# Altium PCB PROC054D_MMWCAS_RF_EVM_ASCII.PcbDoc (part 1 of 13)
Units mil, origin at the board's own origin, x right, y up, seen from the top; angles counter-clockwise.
Board outline 6299.21 x 5370.07 mil, 8 copper layers (L1 TOP, L2 GND, L3 SIGNAL 1, L4 GND, L5 SIGNAL 2, L6 SIGNAL 3, L7 GND, L8 BOTTOM), stack 53.5 mil thick; 775 components, 552 nets, 2648 pads, 7845 vias.
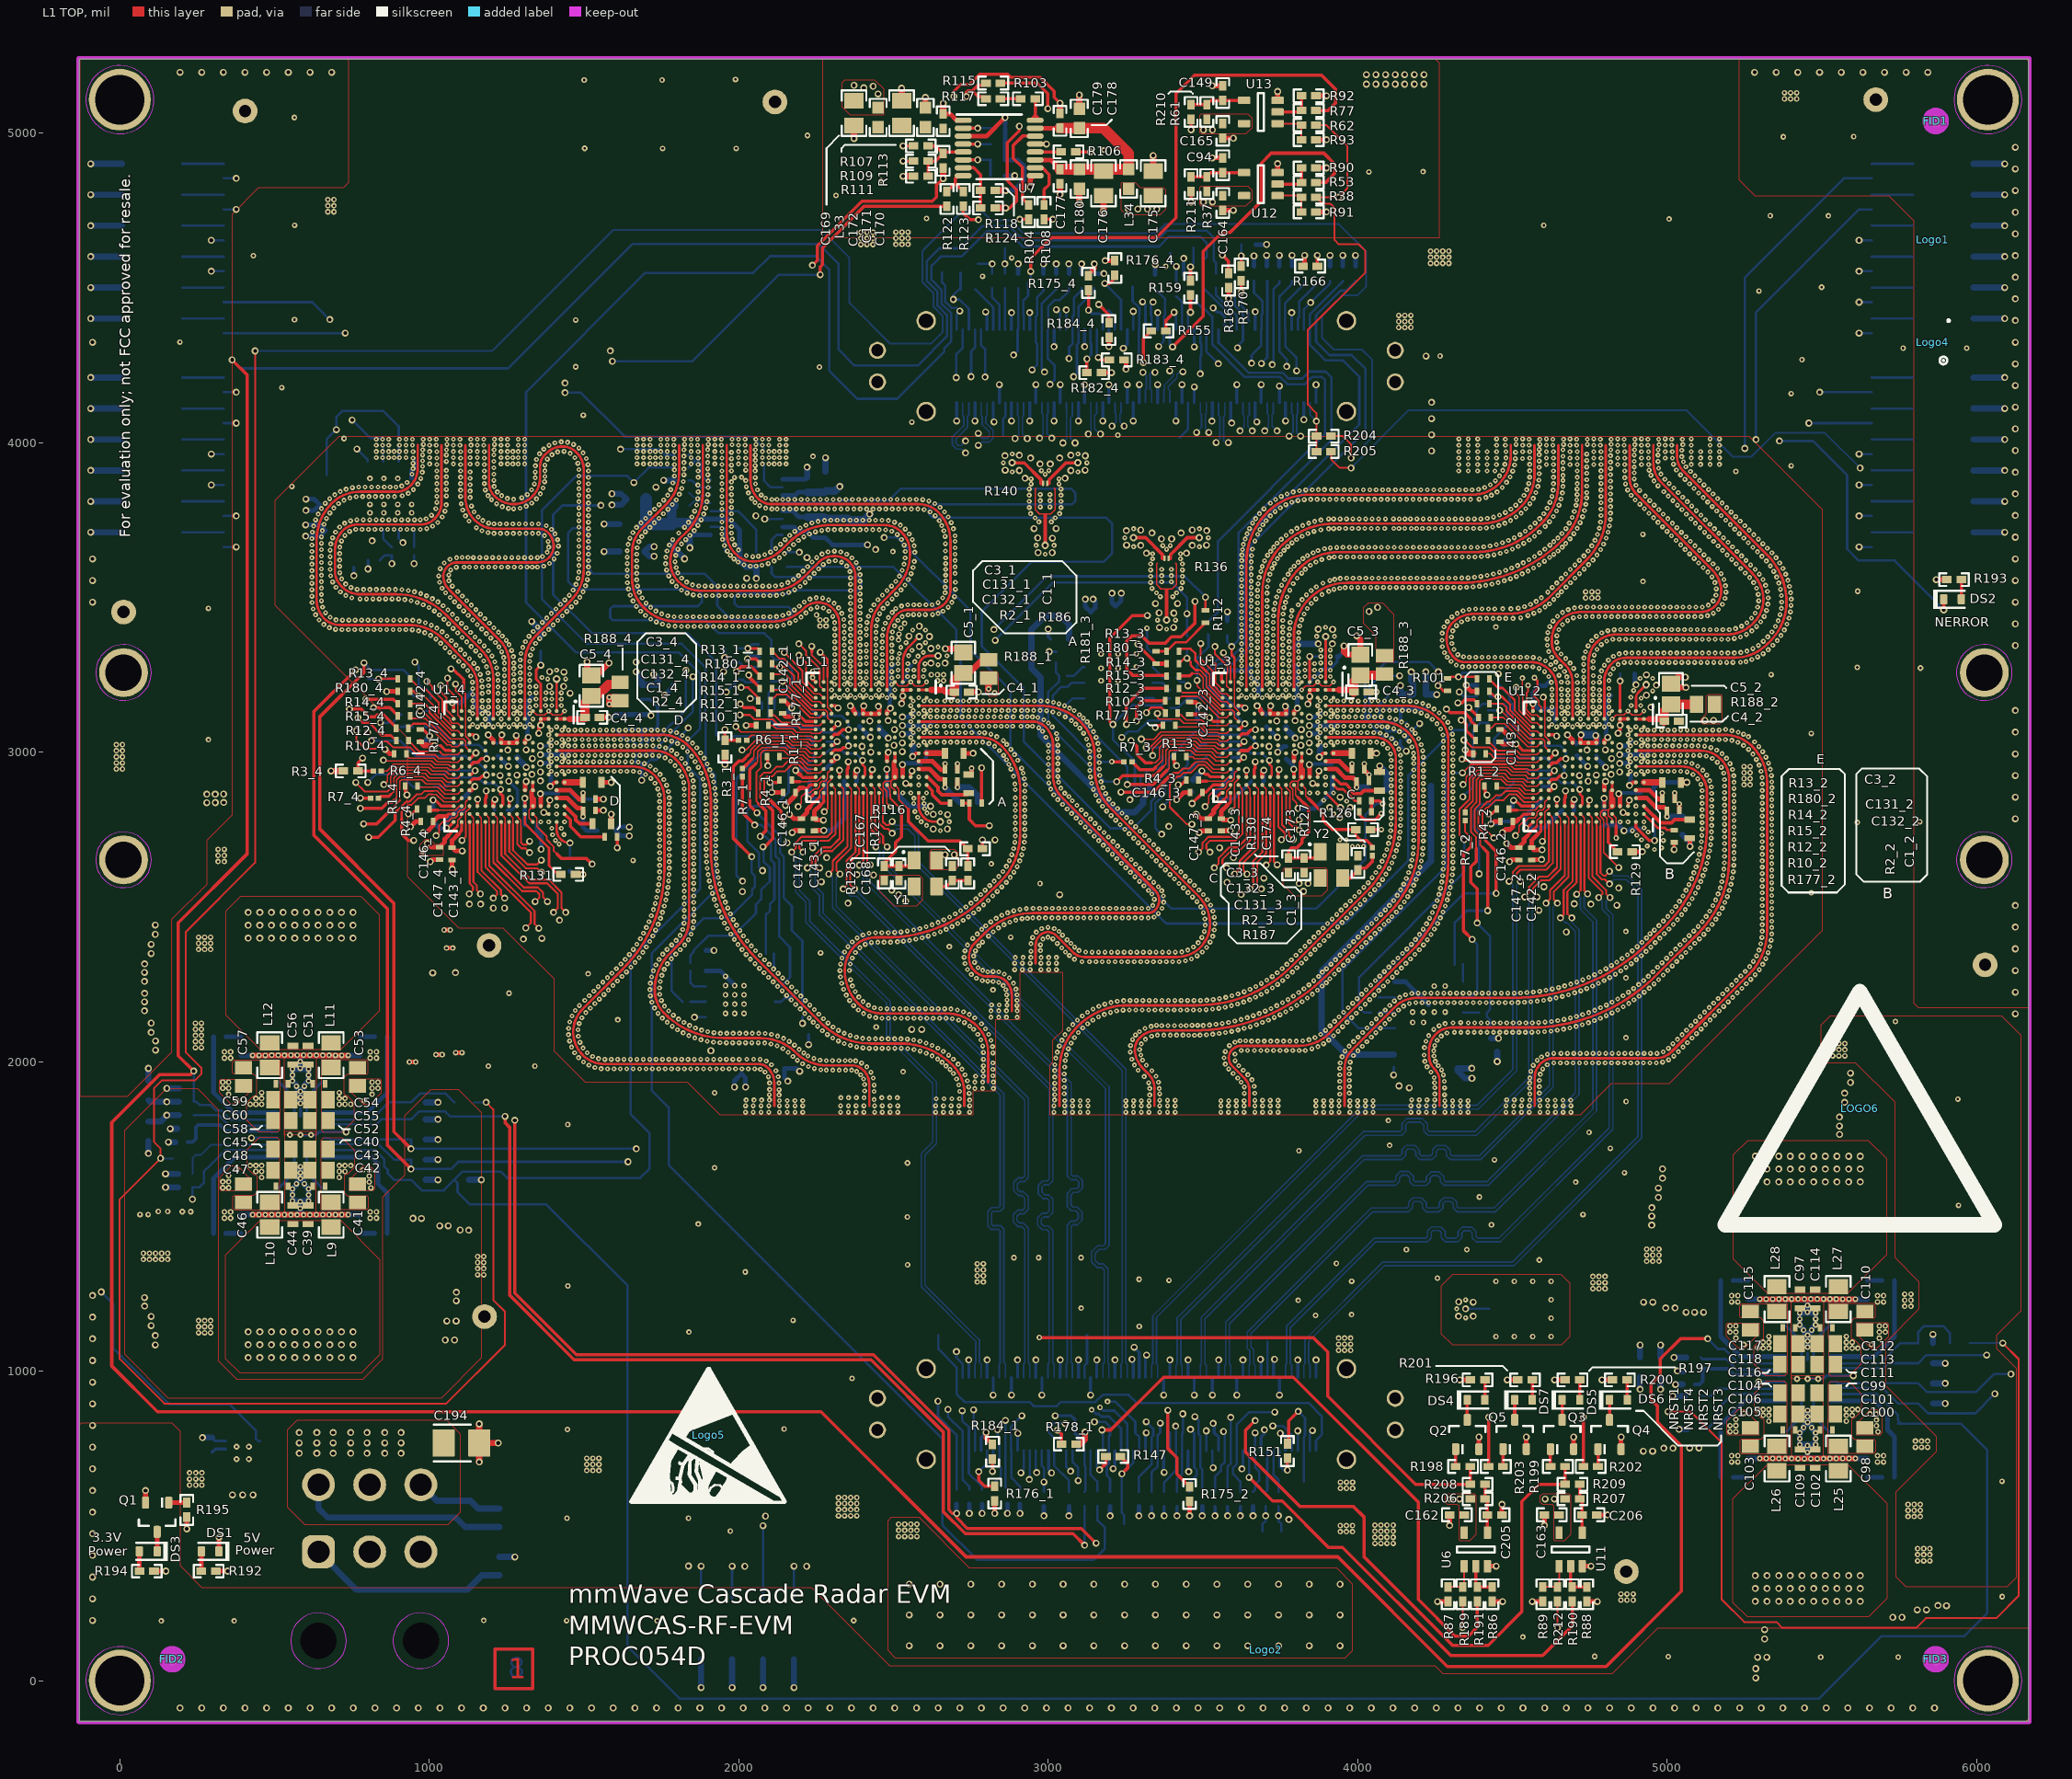
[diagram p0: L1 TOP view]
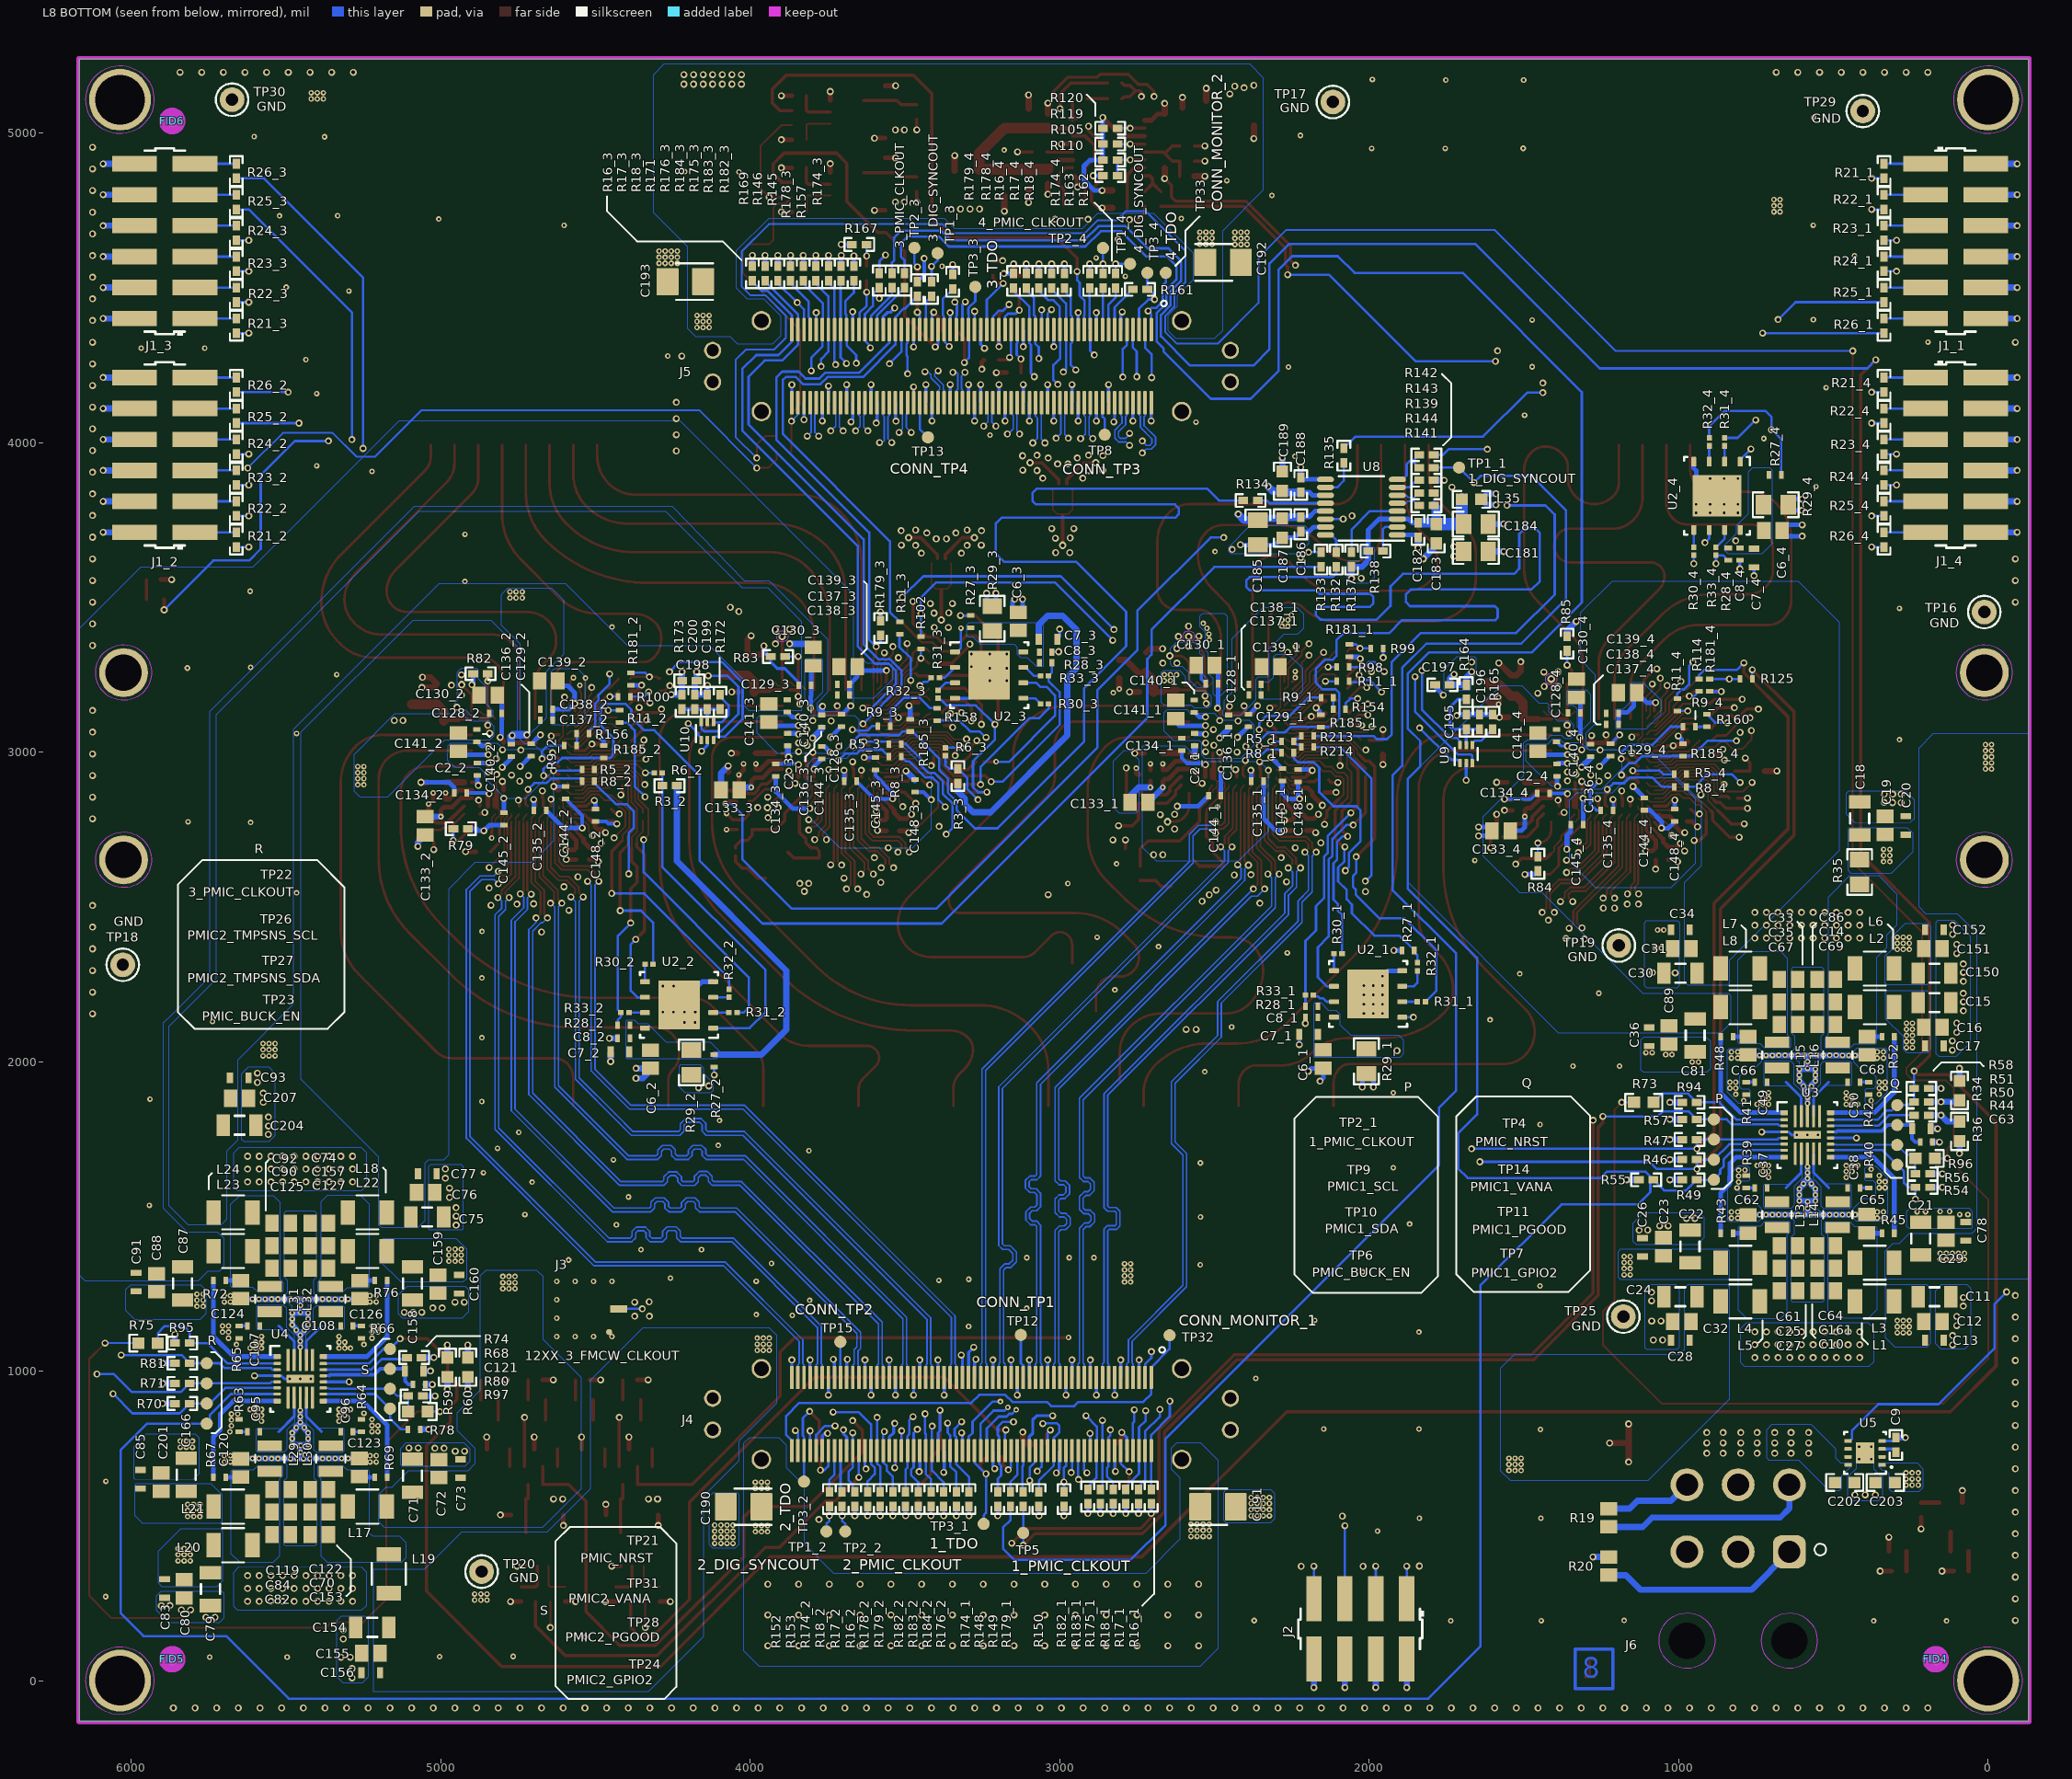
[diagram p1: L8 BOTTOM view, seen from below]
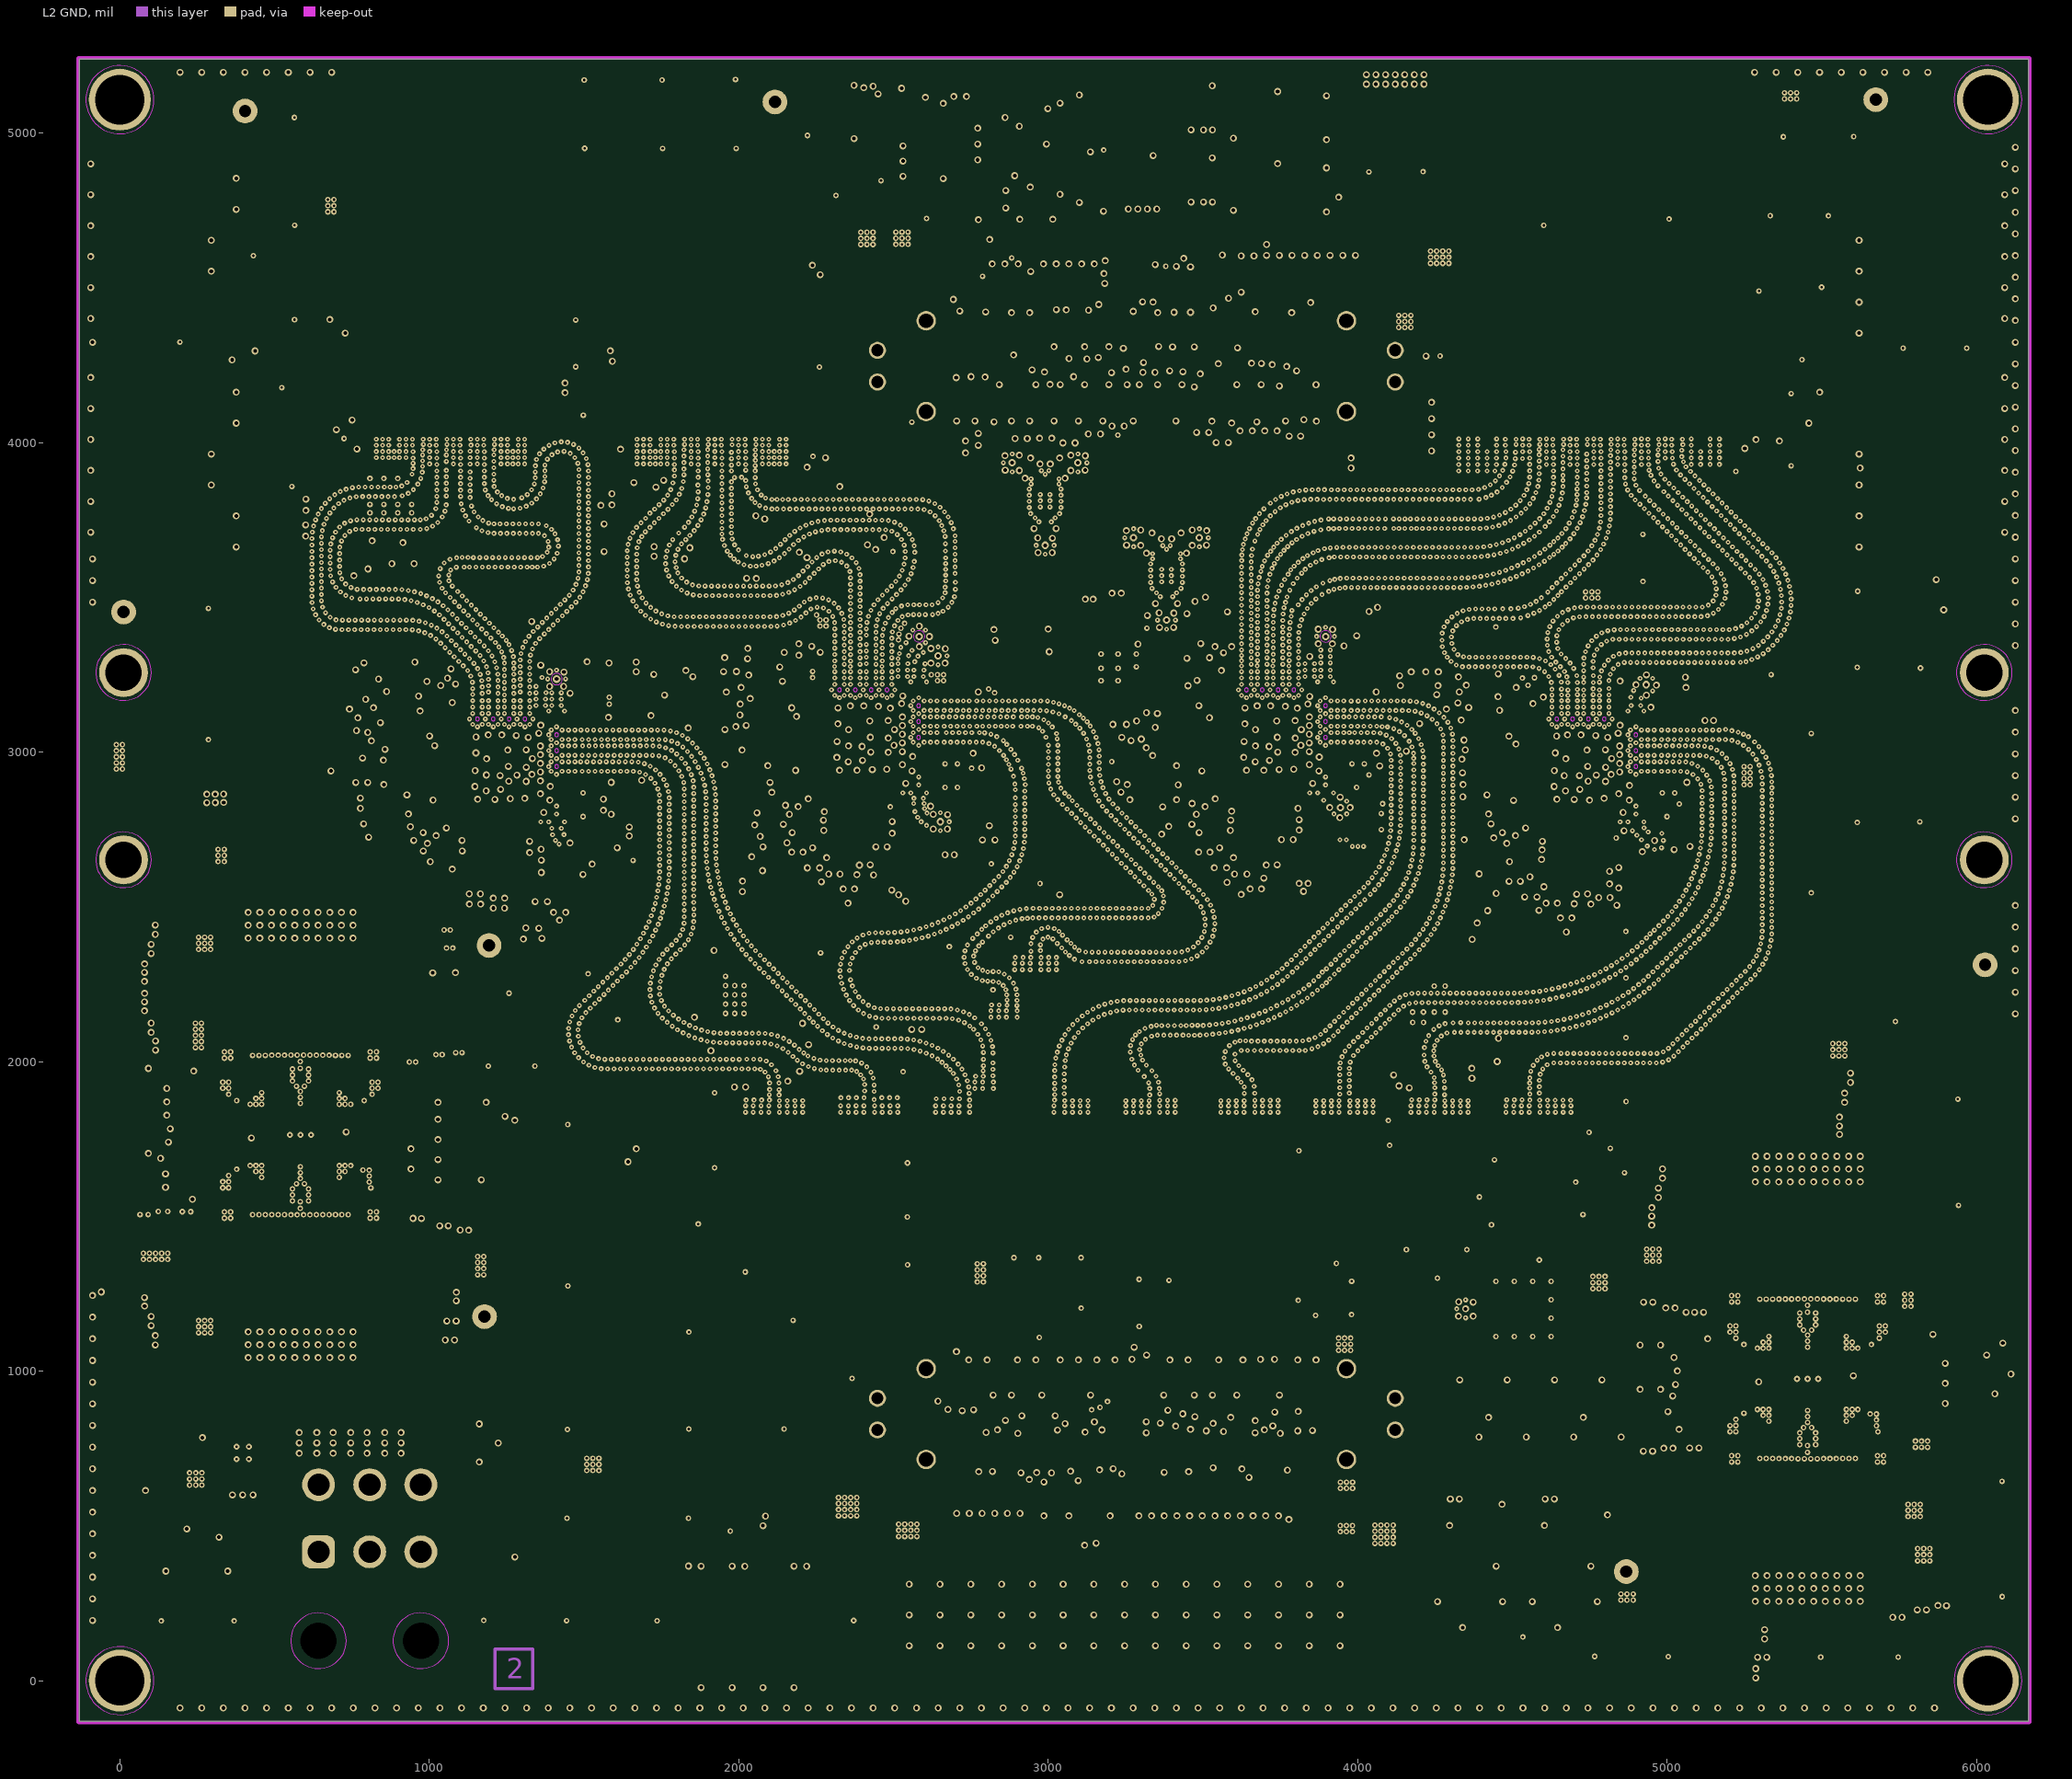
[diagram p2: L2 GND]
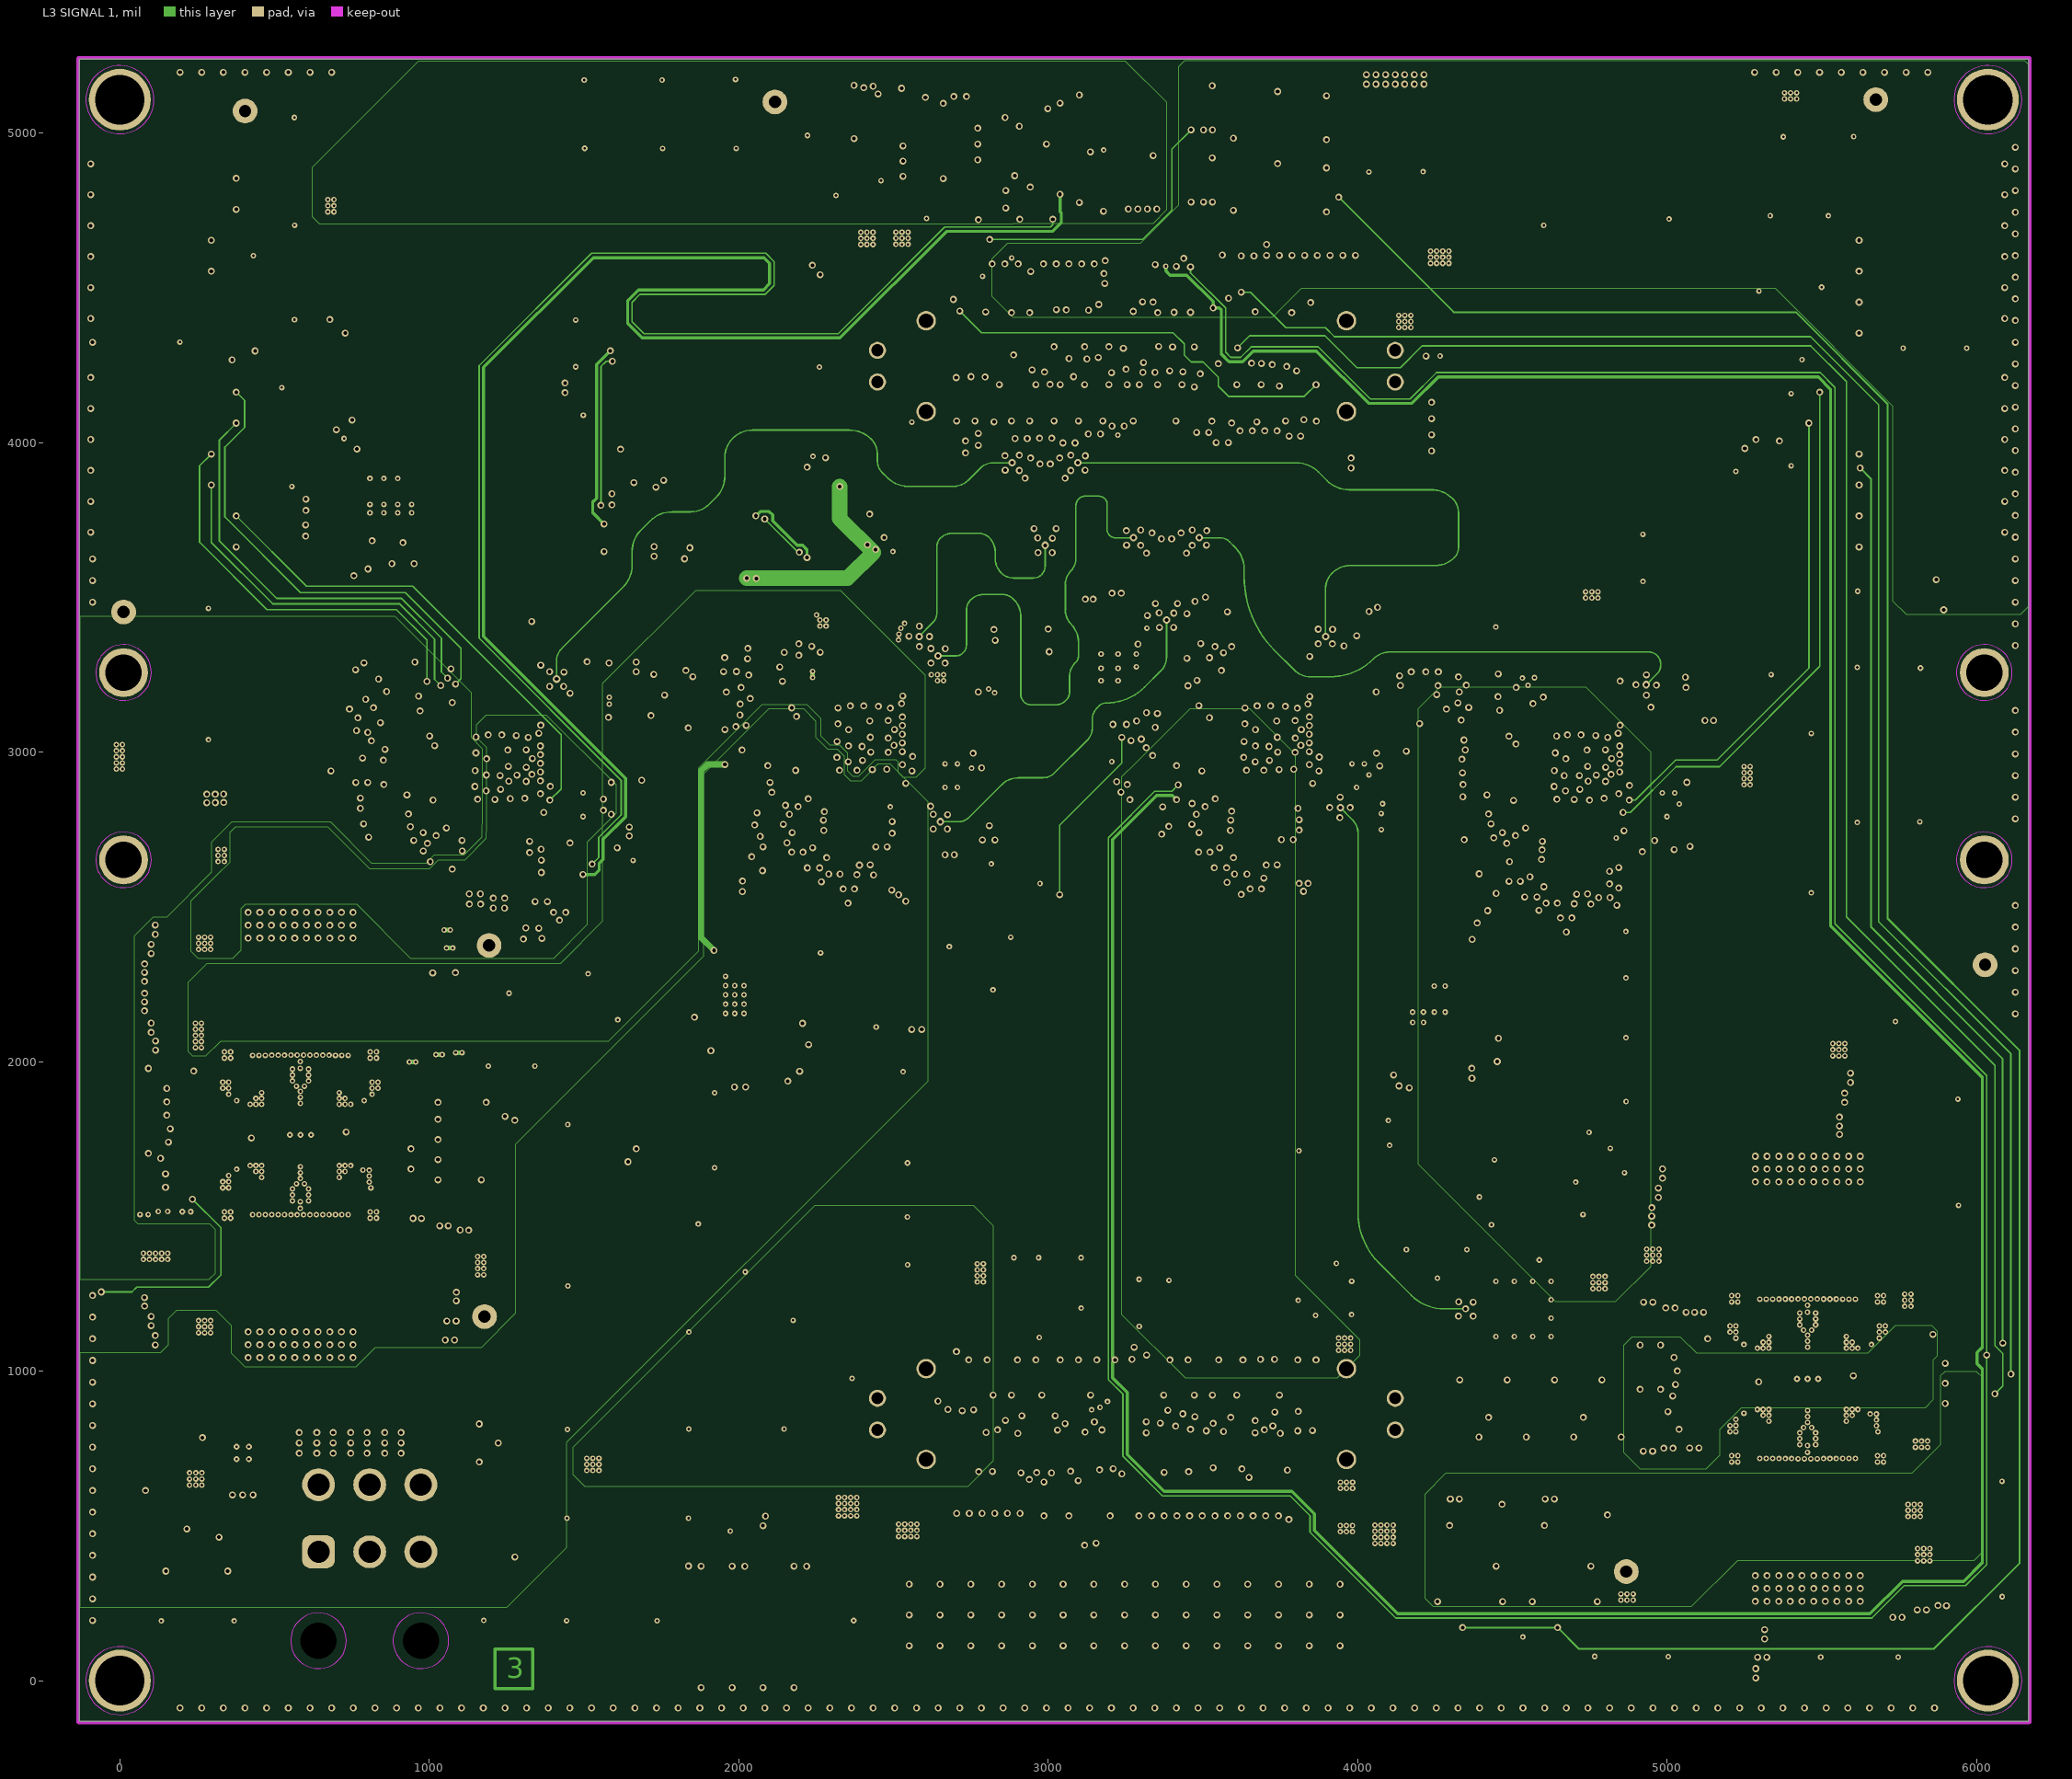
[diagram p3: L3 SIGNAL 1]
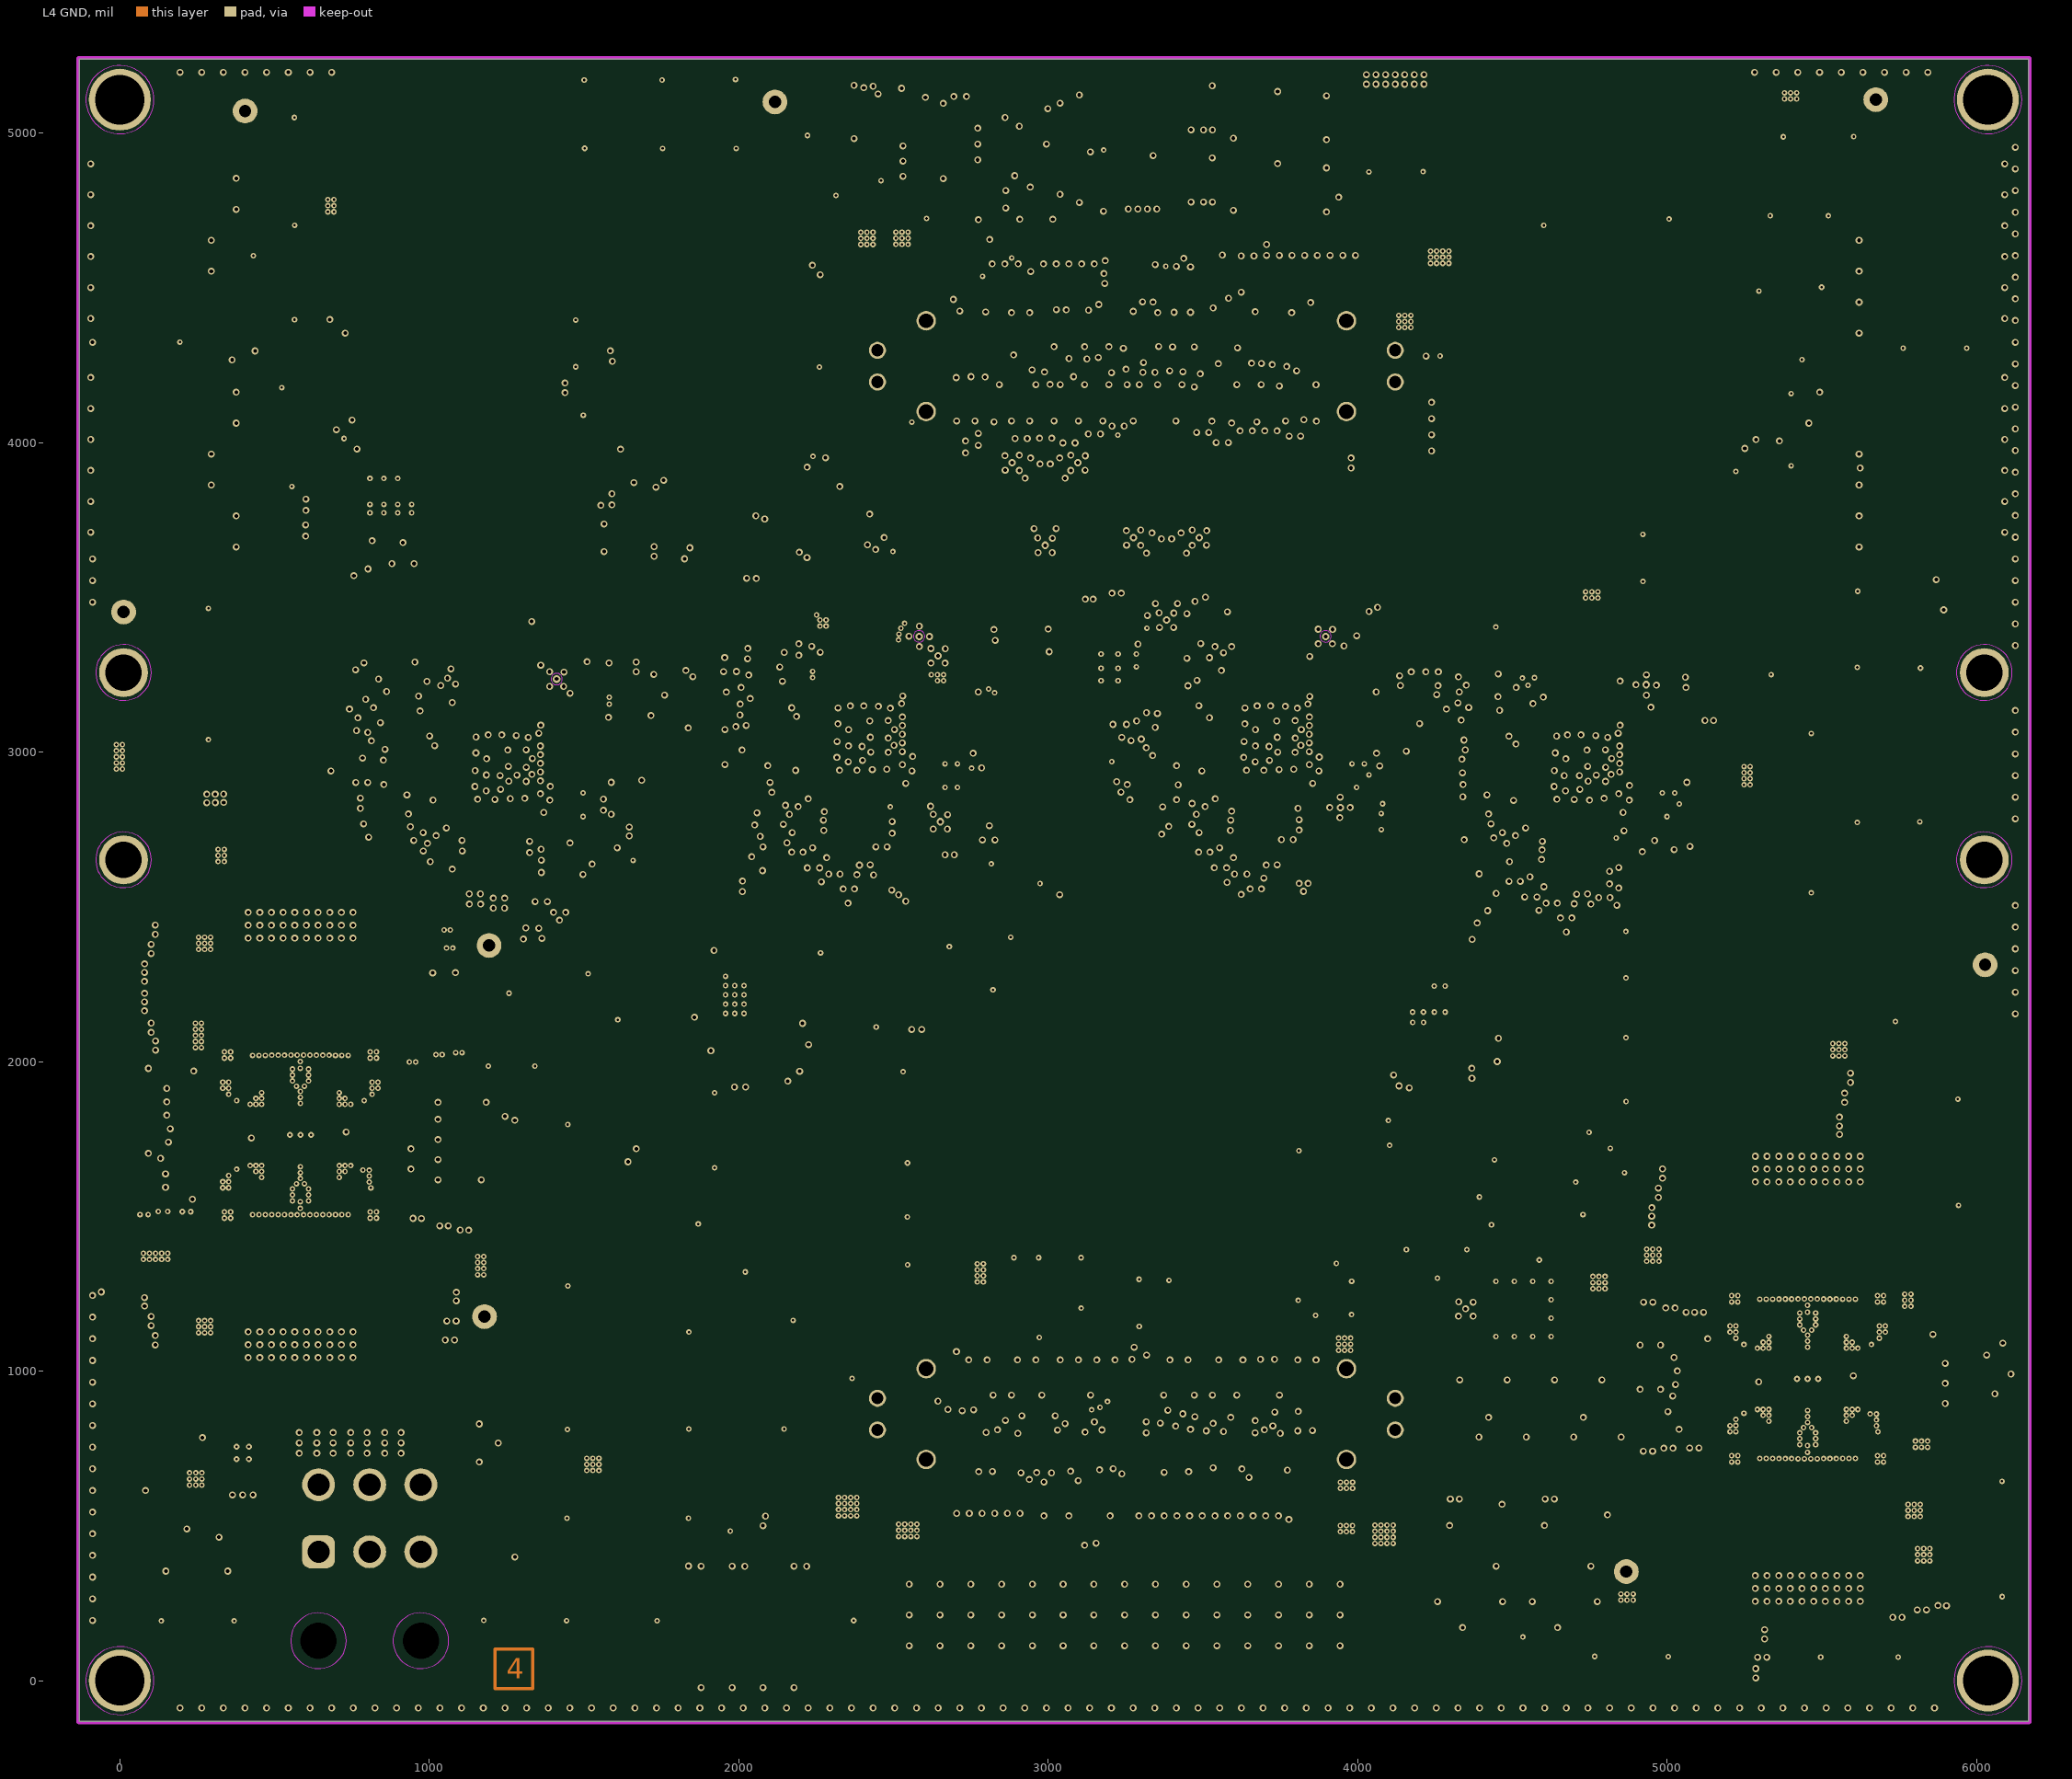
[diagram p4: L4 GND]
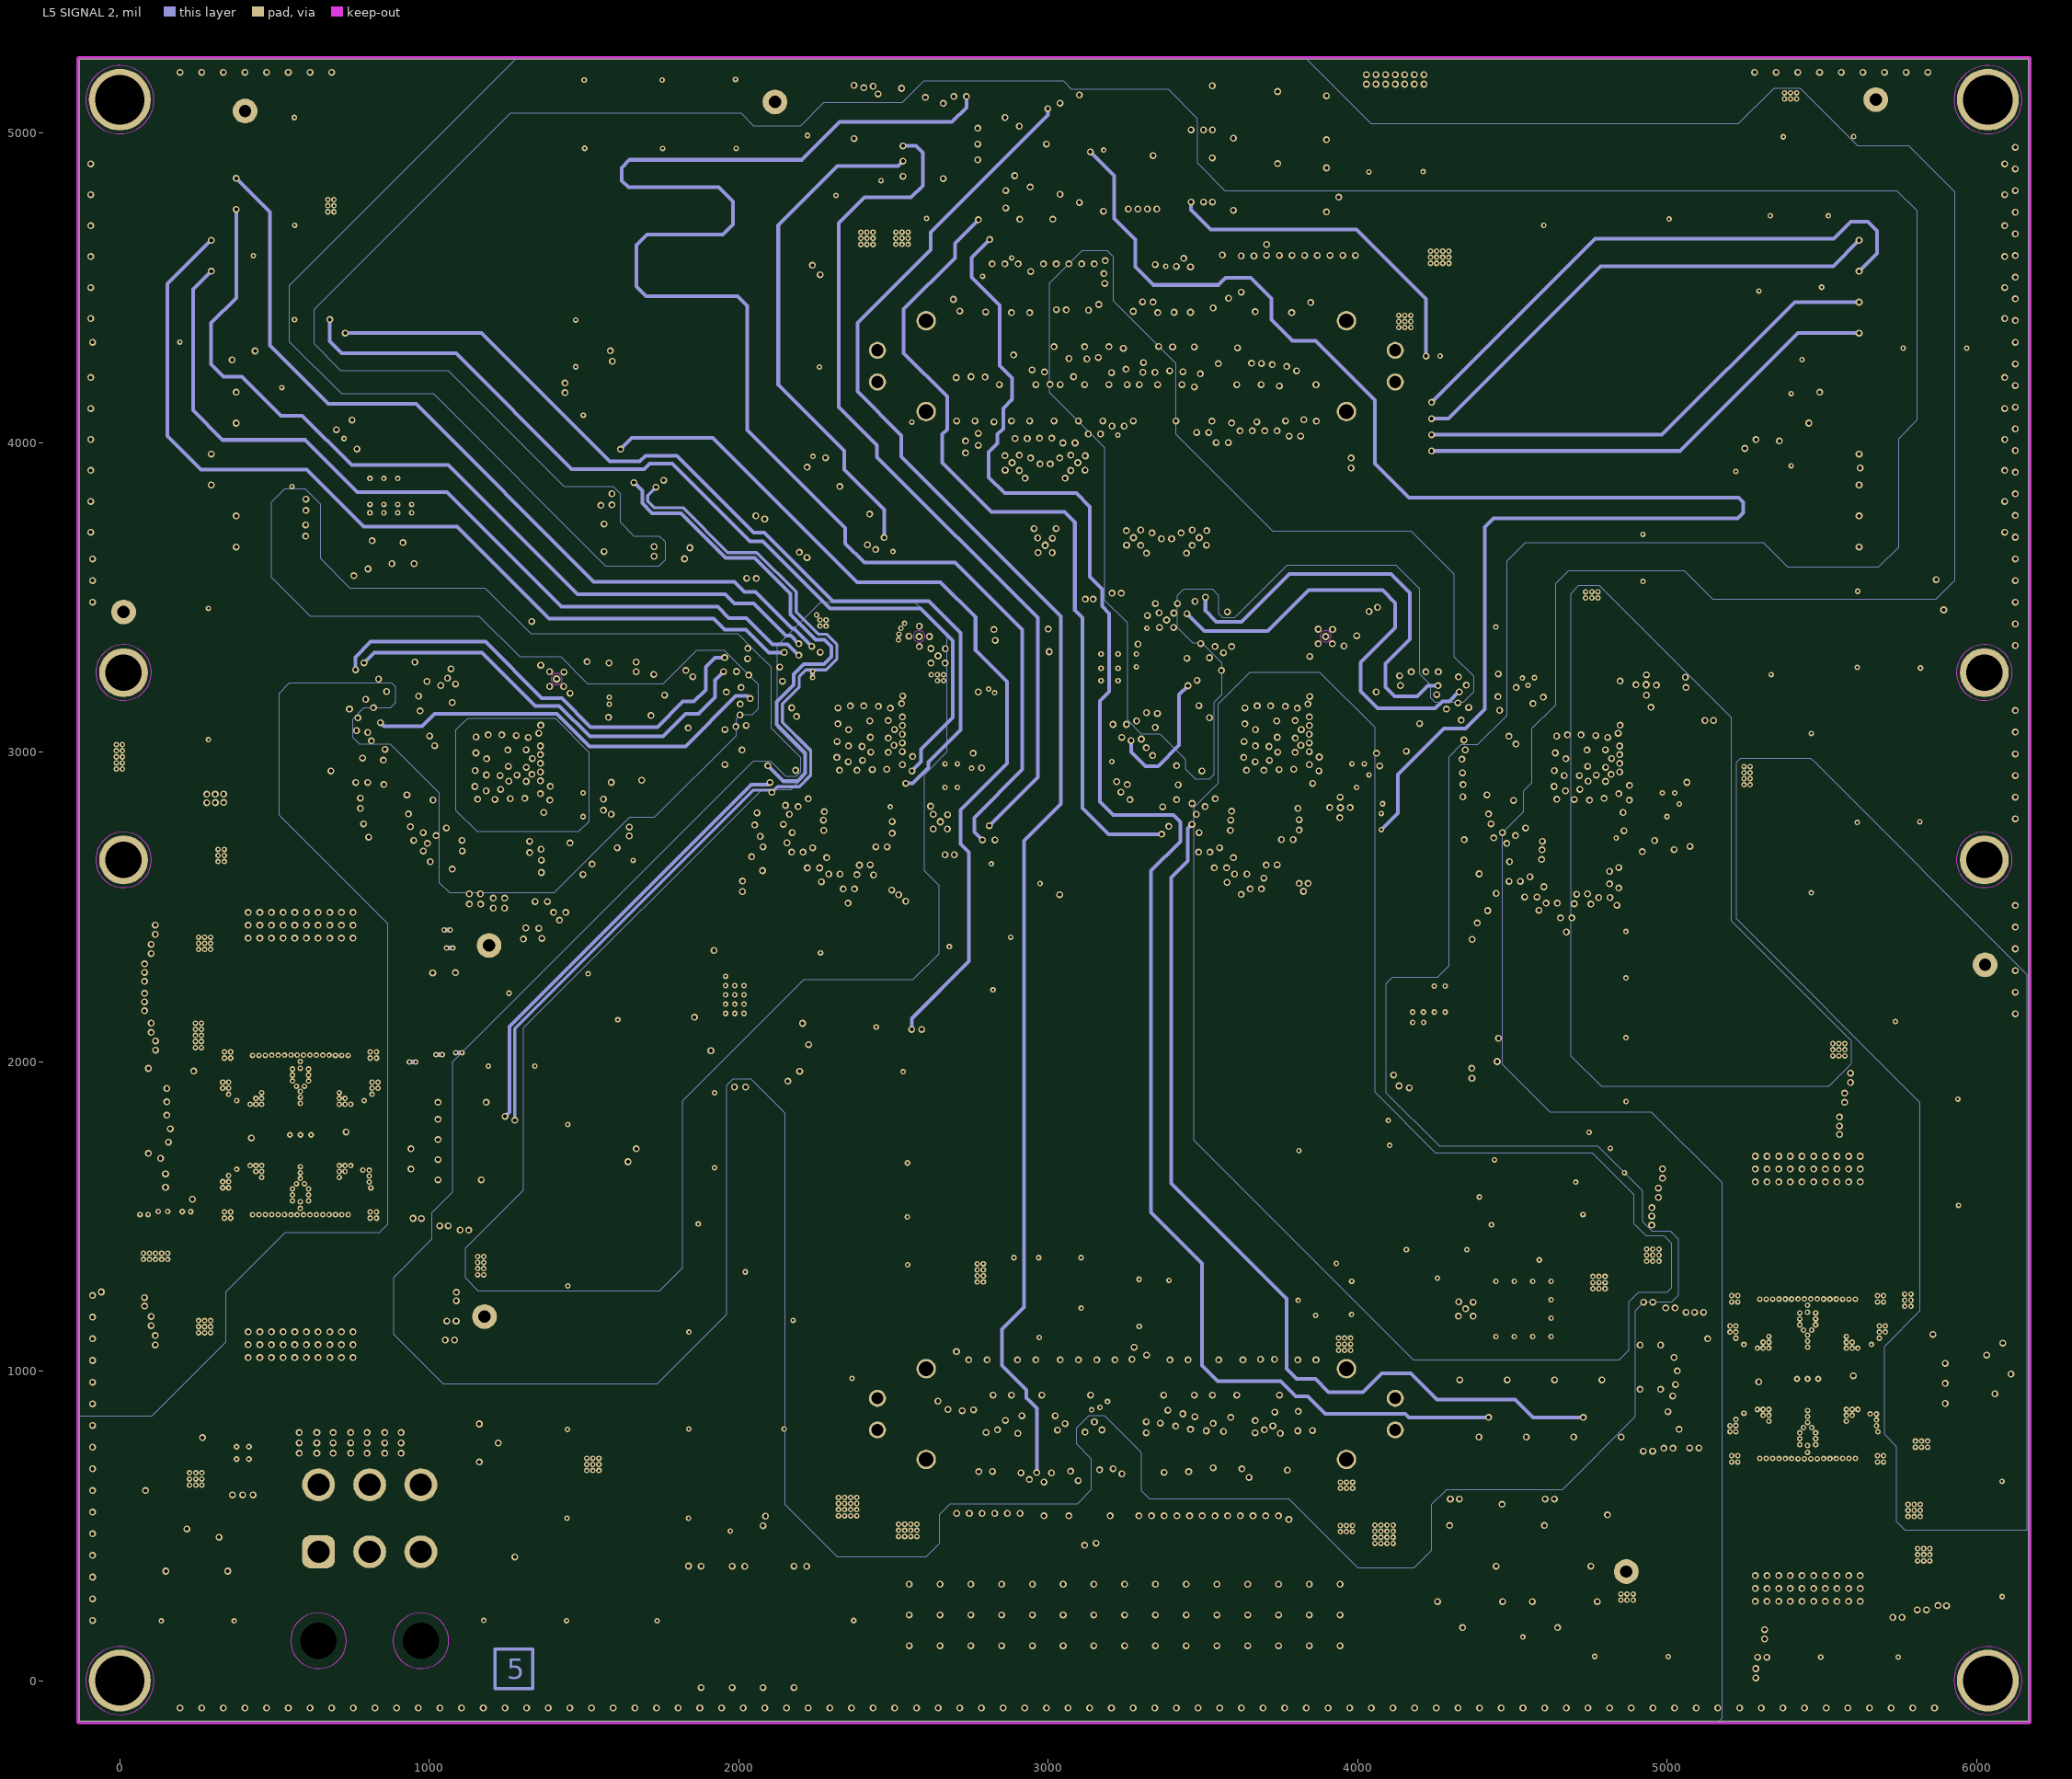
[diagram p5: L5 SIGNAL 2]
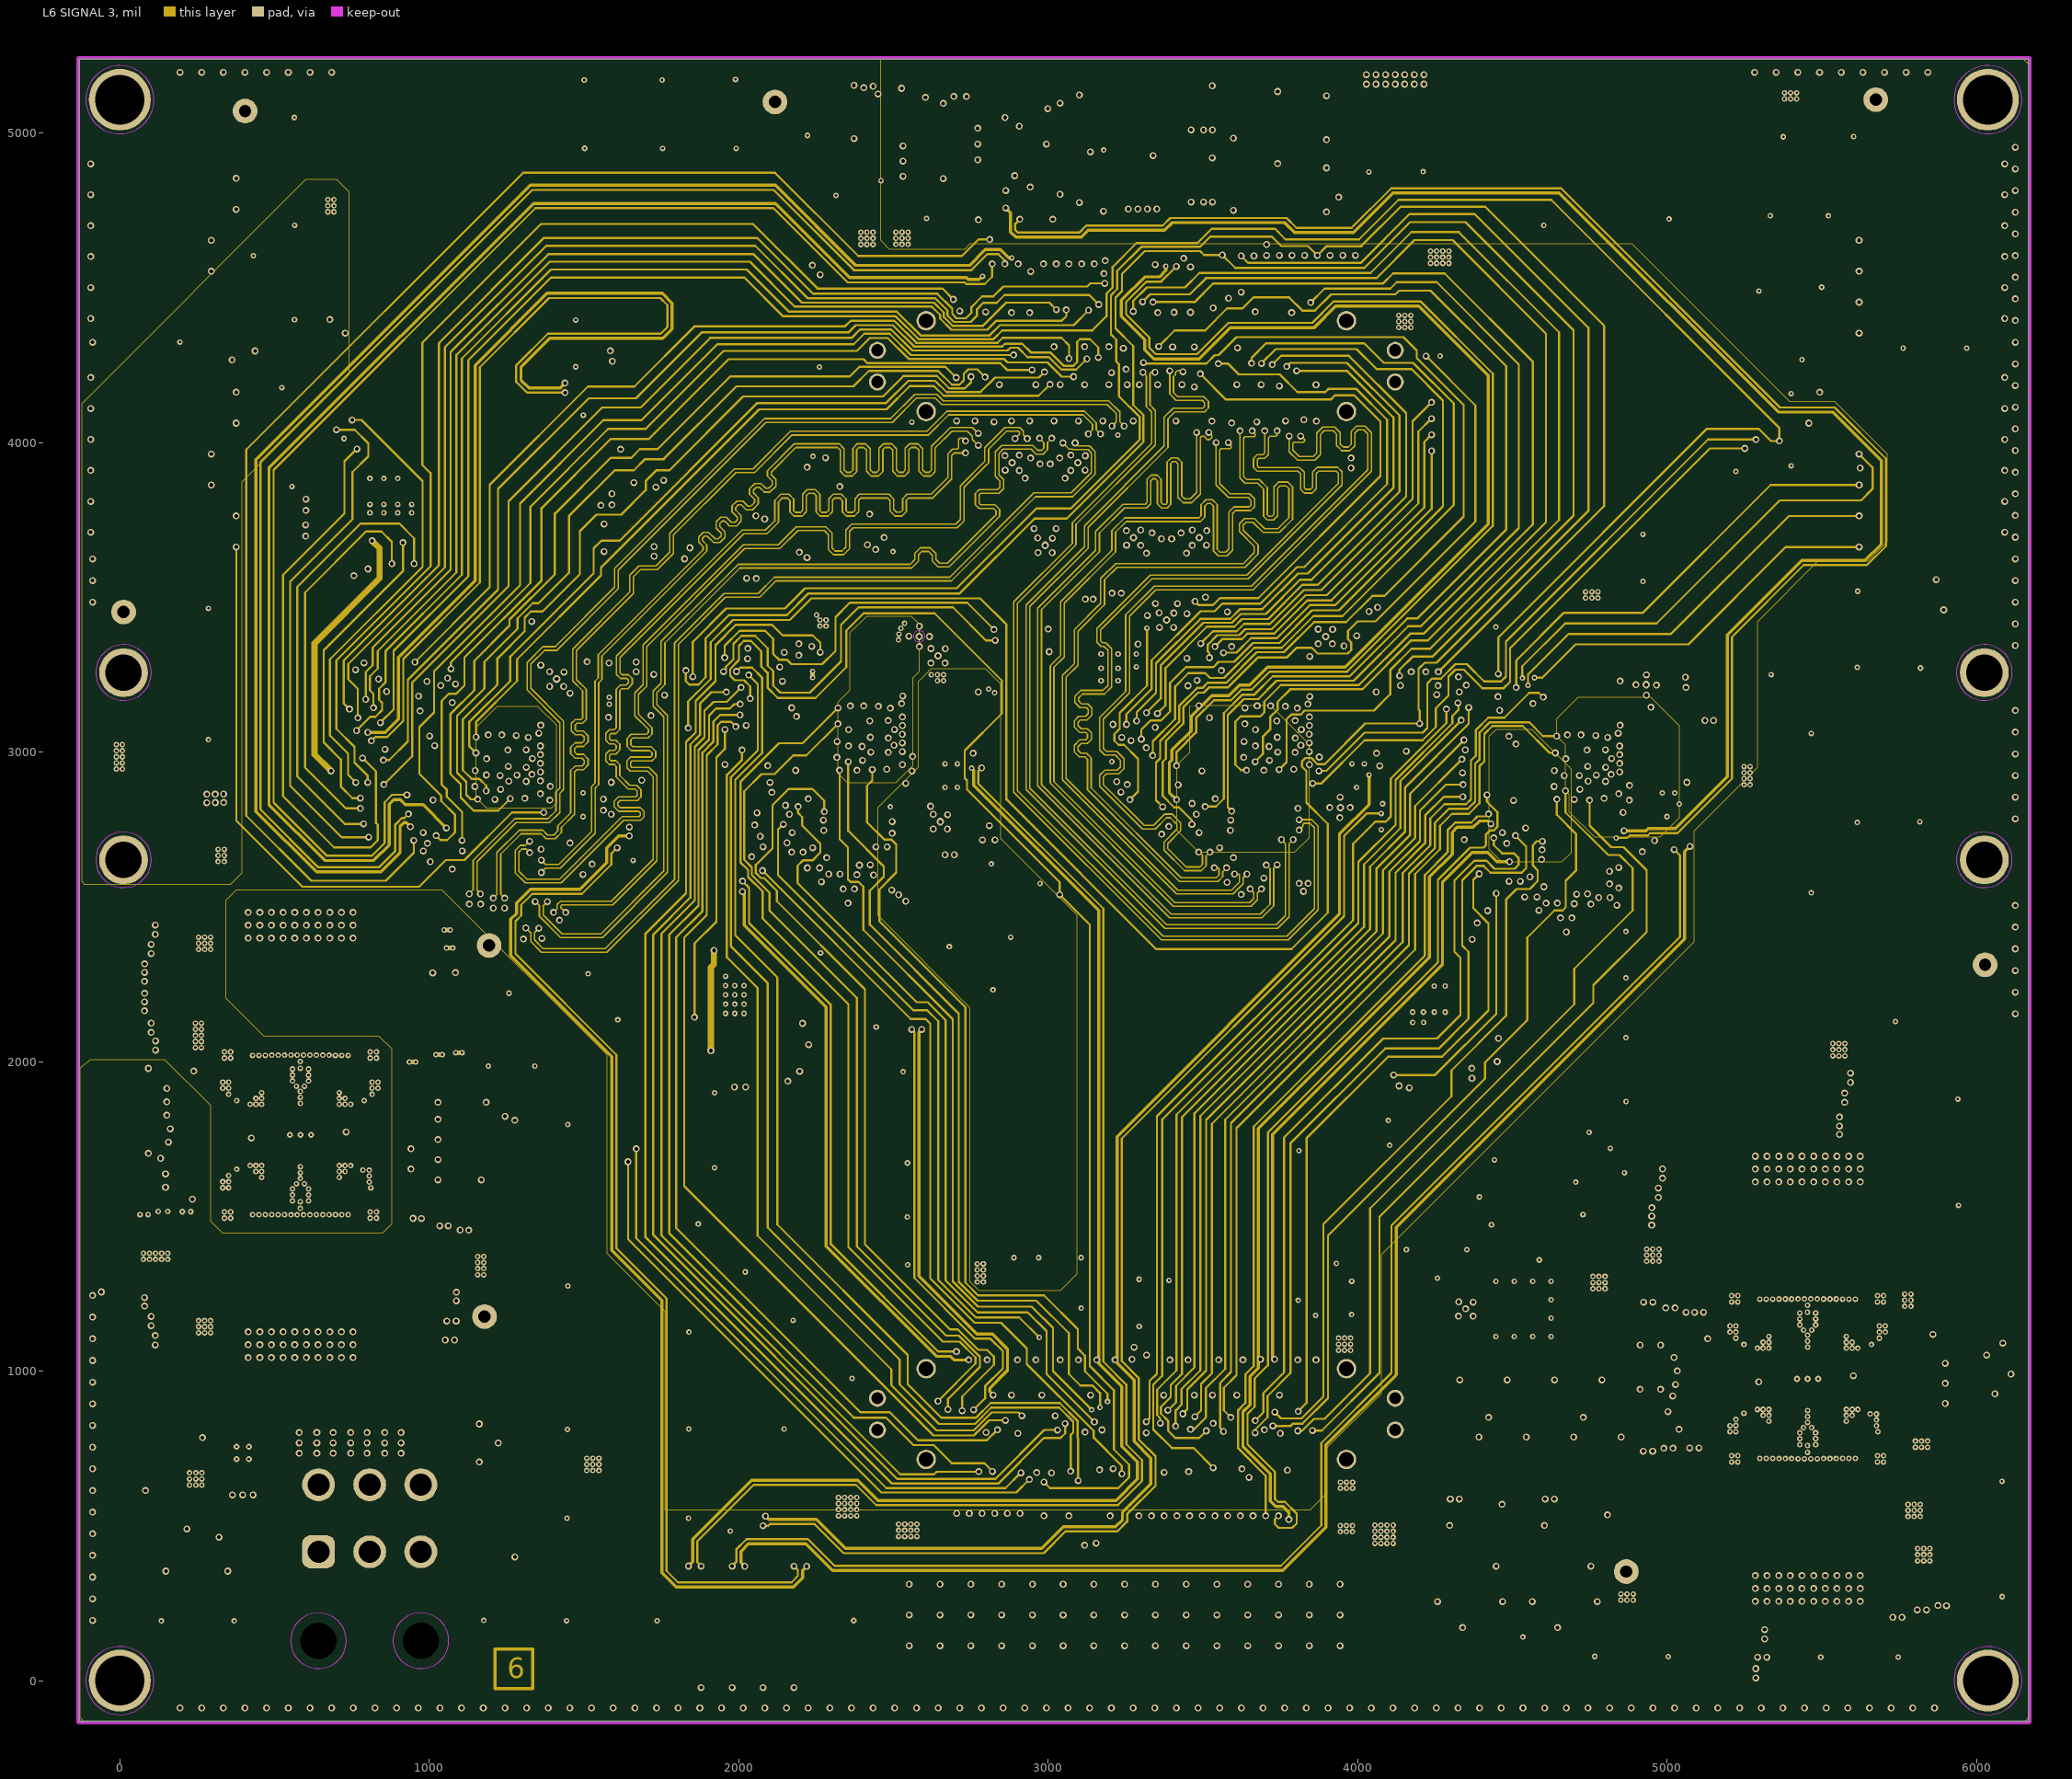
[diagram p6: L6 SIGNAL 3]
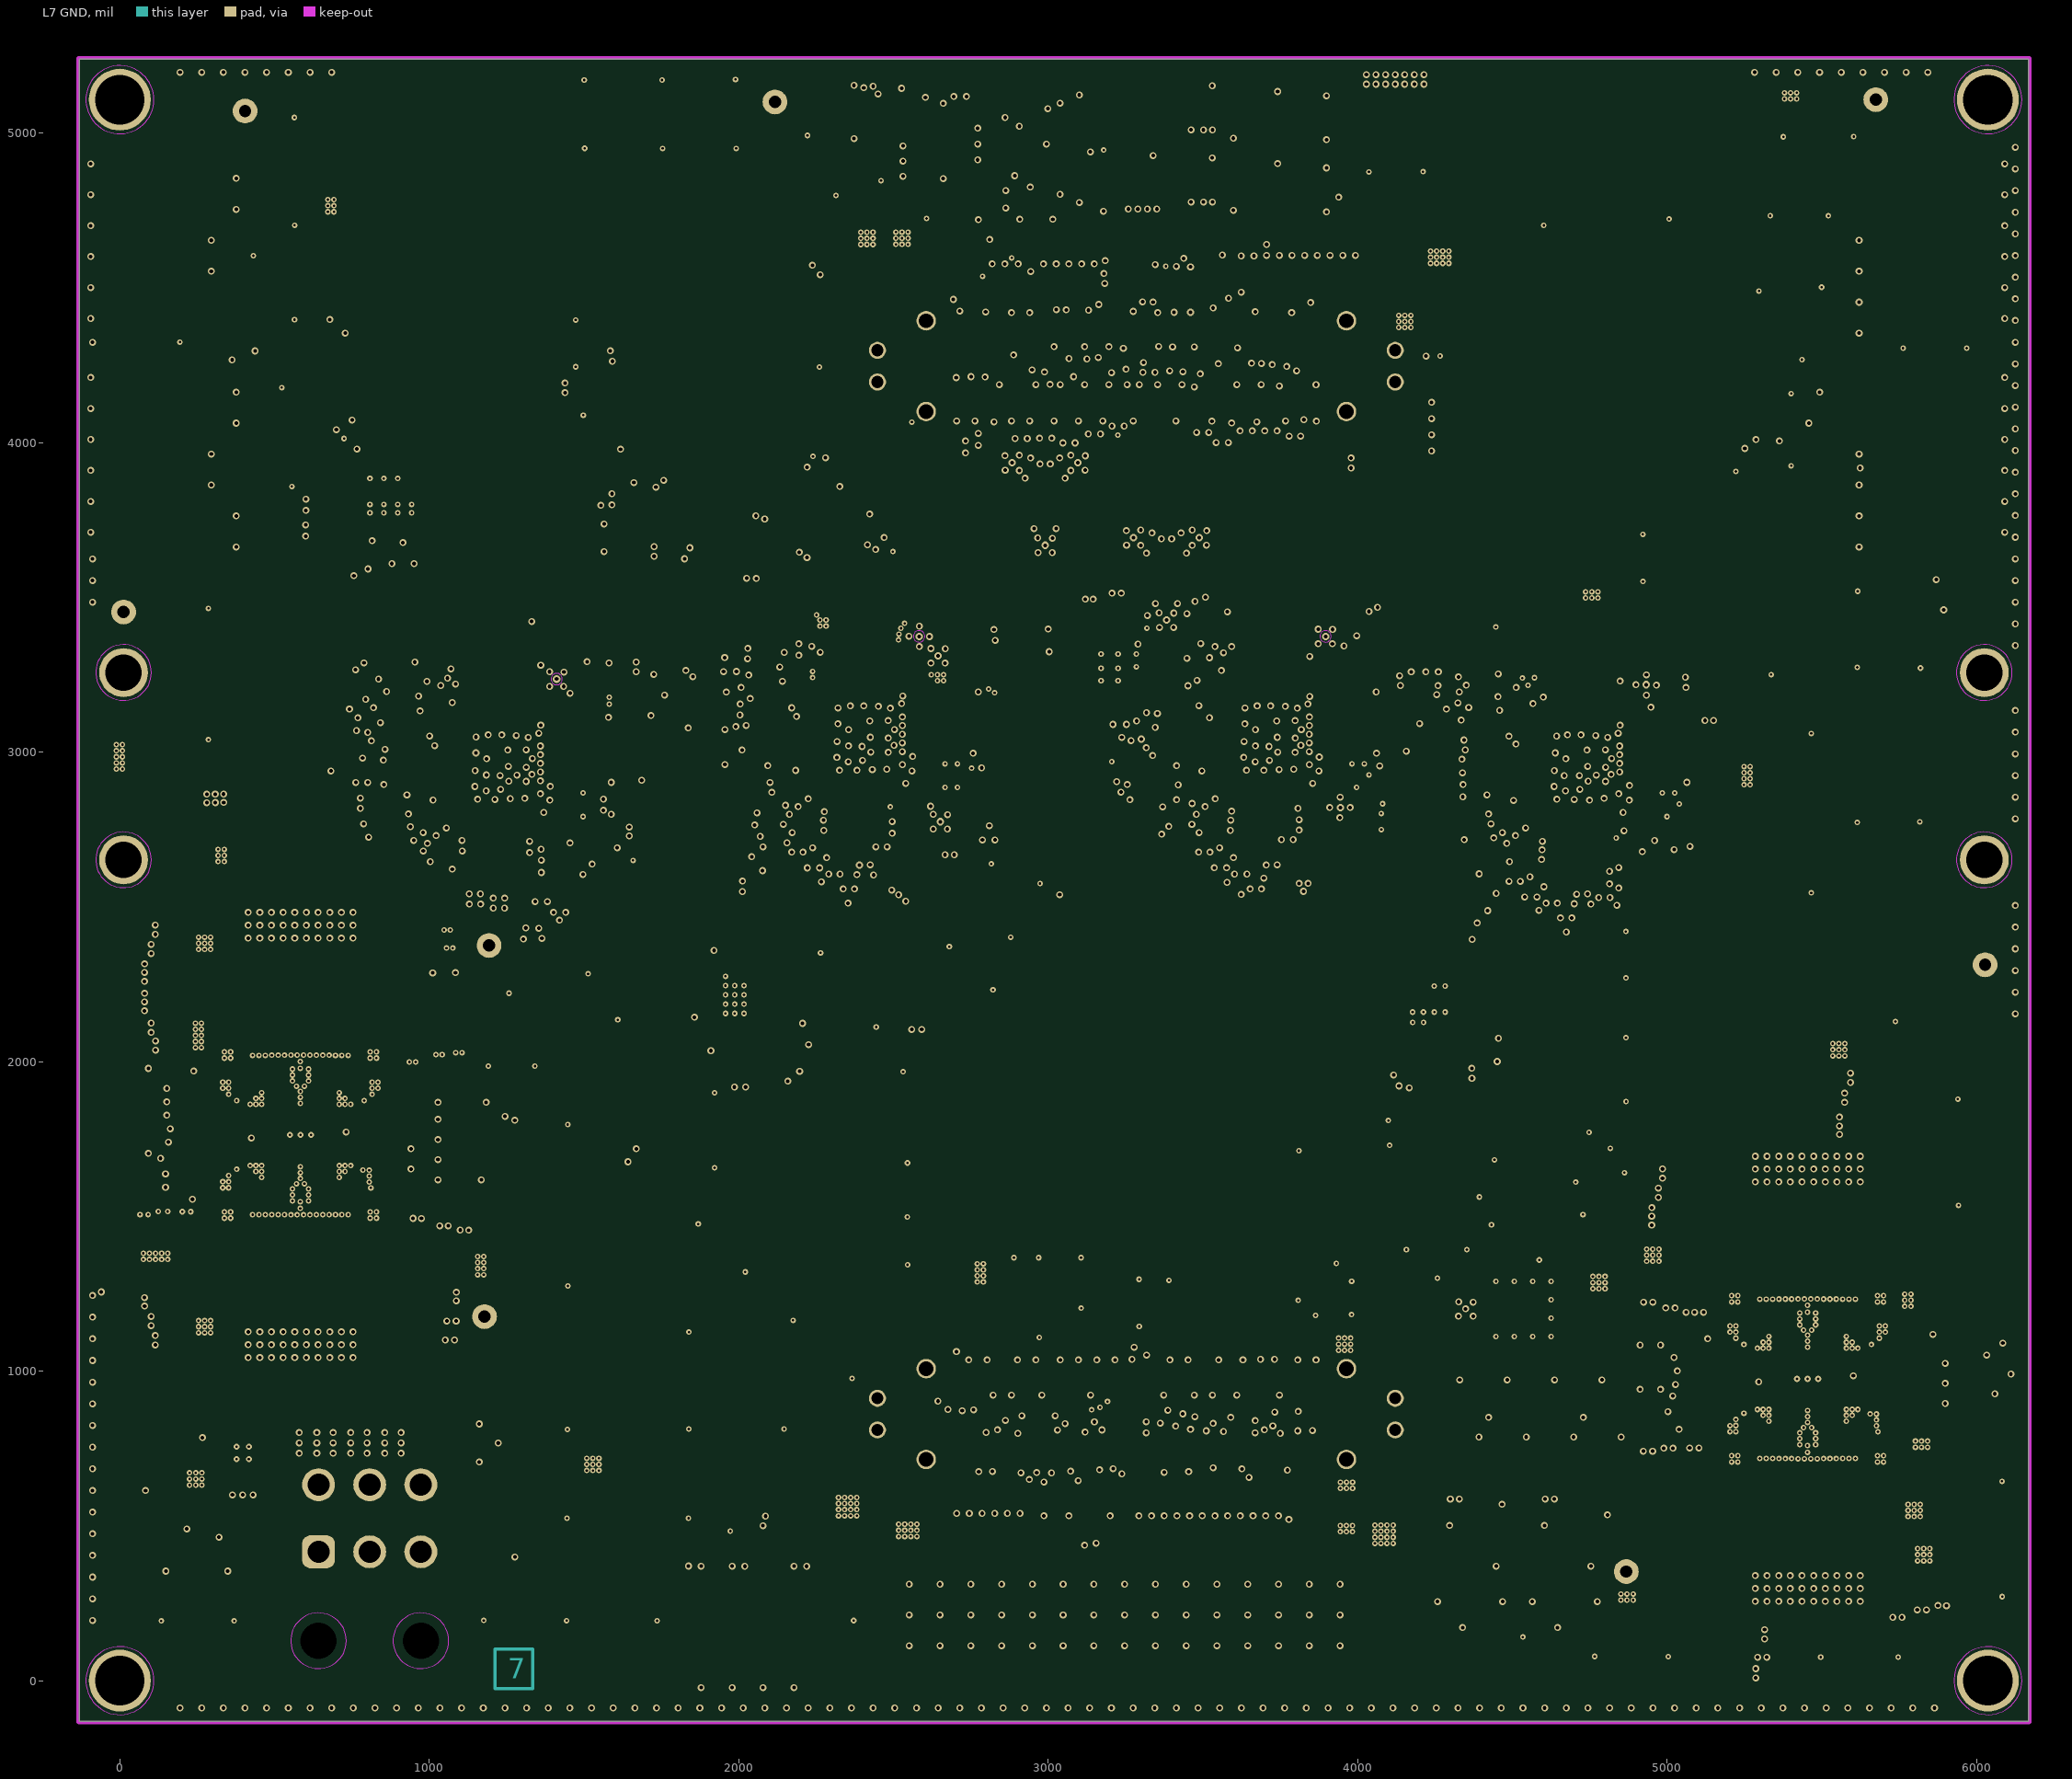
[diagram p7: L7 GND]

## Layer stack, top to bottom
Top Solder: solder mask 0.8, Solder Resist, Dk 3.5
L1 TOP: signal copper 1.6
Dielectric 1: core 5, RO3003, Dk 3
L2 GND: signal copper 0.8
Dielectric2: prepreg 5, RO4450F, Dk 4.2
L3 SIGNAL 1: signal copper 0.6
Dielectric3: core 10.7, RO4835 LOPRO, Dk 3.66
L4 GND: signal copper 0.6
Dielectric4: prepreg 5, 370HR, Dk 4.2
L5 SIGNAL 2: signal copper 1.2
Dielectric5: core 10, 370HR, Dk 4.34
L6 SIGNAL 3: signal copper 0.6
Dielectric6: prepreg 5, 370HR, Dk 4.2
L7 GND: signal copper 0.8
Dielectric7: core 5, 370HR, Dk 4.34
L8 BOTTOM: signal copper 1.6
Bottom Solder: solder mask 0.8, Solder Resist, Dk 3.5

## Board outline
-131,-131 6168.21,-131 6168.21,5239.07 -131,5239.07

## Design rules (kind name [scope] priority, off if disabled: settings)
AcuteAngle [All] p0: scope1count=1 scope1_0_kind=Board scope1_0_value=Board scope2count=1 scope2_0_kind=Board scope2_0_value=Board commentlength=0 minimum=4.00000000000000E+0001
AcuteAngle [All] p1: minimum=4.00000000000000E+0001 checktracksonly=TRUE
AssemblyTestPointUsage [All] p0: scope1count=1 scope1_0_kind=Board scope1_0_value=Board scope2count=1 scope2_0_kind=Board scope2_0_value=Board commentlength=0
AssemblyTestpoint [All] p0: scope1count=1 scope1_0_kind=Board scope1_0_value=Board scope2count=1 scope2_0_kind=Board scope2_0_value=Board commentlength=0
BoardOutlineClearance [All] p0: scope1count=1 scope1_0_kind=Board scope1_0_value=Board scope2count=1 scope2_0_kind=Board scope2_0_value=Board commentlength=0 gap=25
BoardOutlineClearance [All] p1: gap=25 ignorepadtopadclearanceinfootprint=FALSE except(0: Text-OutlineEdge Text-CavityEdge Text-CutoutEdge Text-SplitBarrior Text-SplitContinuation)
Clearance Clearance_FMCW_L3_All [All] p0 off: scope1count=1 scope1_0_kind=Board scope1_0_value=Board scope2count=1 scope2_0_kind=Board scope2_0_value=Board commentlength=104 gap=50 // Protel DXP Scope 1 Expression Was: InNetClass('FMCW') and (istrack or IsArc)  and InLayerClass('L3')
Clearance Clearance_GND-Pad [All] p0 off: scope1count=1 scope1_0_kind=Board scope1_0_value=Board scope2count=1 scope2_0_kind=Board scope2_0_value=Board commentlength=45 gap=9 // Protel DXP Scope 2 Expression Was: InPoly
Clearance Clearance_L8_Diff_4W [All] p0 off: scope1count=1 scope1_0_kind=Board scope1_0_value=Board scope2count=1 scope2_0_kind=Board scope2_0_value=Board commentlength=73 gap=21 // Protel DXP Scope 2 Expression Was: Istrack and InLayerClass('Bottom')
Clearance Clearance_L6_Diff_4W [All] p0 off: scope1count=1 scope1_0_kind=Board scope1_0_value=Board scope2count=1 scope2_0_kind=Board scope2_0_value=Board commentlength=69 gap=16 // Protel DXP Scope 2 Expression Was: Istrack and InLayerClass('L6')
Clearance "Clearance_Power Divider_1" [All] p0 off: scope1count=1 scope1_0_kind=Board scope1_0_value=Board scope2count=1 scope2_0_kind=Board scope2_0_value=Board commentlength=87 gap=8 // Protel DXP Scope 2 Expression Was: InNet('GND') and InLayerClass('Top')  and InPoly
Clearance "Clearance_Power Divider" [All] p0 off: scope1count=1 scope1_0_kind=Board scope1_0_value=Board scope2count=1 scope2_0_kind=Board scope2_0_value=Board commentlength=115 gap=7 // Protel DXP Scope 1 Expression Was: InLayerClass('Top') and All and (WithinRoom('Room5') or WithinRoom('Room6'))
Clearance Clearance_FMCW_L3_All_Room [All] p0 off: scope1count=1 scope1_0_kind=Board scope1_0_value=Board scope2count=1 scope2_0_kind=Board scope2_0_value=Board commentlength=227 gap=8 // Protel DXP Scope 2 Expression Was: IsVia and (WithinRoom('A1') or WithinRoom('A2') or WithinRoom('A3') or WithinRoom('A4') or WithinRoom('A5') or WithinRoom('A6') or WithinRoom('A7') or WithinRoom('A8') or WithinRoom('A9'))
Clearance Clearance_20GHz [All] p0 off: scope1count=1 scope1_0_kind=Board scope1_0_value=Board scope2count=1 scope2_0_kind=Board scope2_0_value=Board commentlength=62 gap=7 // Protel DXP Scope 2 Expression Was: InPoly and InNet('GND')
Clearance "Clearance_Internal Poly" [All] p0 off: scope1count=1 scope1_0_kind=Board scope1_0_value=Board scope2count=1 scope2_0_kind=Board scope2_0_value=Board commentlength=139 gap=5 // Protel DXP Scope 2 Expression Was: isvia and (WithinRoom('Room1') or WithinRoom('Room2') or WithinRoom('Room3') or WithinRoom('Room4'))
Clearance Clearance_FMCW_L3_Poly [All] p0 off: scope1count=1 scope1_0_kind=Board scope1_0_value=Board scope2count=1 scope2_0_kind=Board scope2_0_value=Board commentlength=80 gap=200 // Protel DXP Scope 2 Expression Was: (isarc or istrack) AND InNetClass('FMCW')
Clearance Clearance_Keepout [All] p0 off: scope1count=1 scope1_0_kind=Board scope1_0_value=Board scope2count=1 scope2_0_kind=Board scope2_0_value=Board commentlength=48 gap=1 // Protel DXP Scope 1 Expression Was: IsKeepOut
Clearance Clearance_Antenna [All] p0 off: scope1count=1 scope1_0_kind=NetClass scope1_0_value=Antenna scope2count=1 scope2_0_kind=Board scope2_0_value=Board commentlength=86 gap=10 // Protel DXP Scope 2 Expression Was: InPoly and InNet('GND') and InLayerClass('Top')
Clearance Clearance_Poly [All] p0 off: scope1count=1 scope1_0_kind=Board scope1_0_value=Board scope2count=1 scope2_0_kind=Board scope2_0_value=Board commentlength=48 gap=10 // Protel DXP Scope 2 Expression Was: InPolygon
Clearance Clearance_BGA [All] p0 off: scope1count=1 scope1_0_kind=Board scope1_0_value=Board scope2count=1 scope2_0_kind=Board scope2_0_value=Board commentlength=137 gap=4 // Protel DXP Scope 1 Expression Was: (WithinRoom('Room1') or WithinRoom('Room2') or WithinRoom('Room3') or WithinRoom('Room4')) and All
Clearance [All] p0: scope1count=1 scope1_0_kind=Board scope1_0_value=Board scope2count=1 scope2_0_kind=Board scope2_0_value=Board commentlength=0 gap=5
Clearance Clearance_L3_4W [All] p0 off: scope1count=1 scope1_0_kind=Board scope1_0_value=Board scope2count=1 scope2_0_kind=Board scope2_0_value=Board commentlength=68 gap=15.3 // Protel DXP Scope 2 Expression Was: InLayerClass('L3') and inpoly
Clearance Clearance_L6_4W [All] p0 off: scope1count=1 scope1_0_kind=Board scope1_0_value=Board scope2count=1 scope2_0_kind=Board scope2_0_value=Board commentlength=68 gap=21 // Protel DXP Scope 2 Expression Was: InLayerClass('L6') and inpoly
Clearance Clearance_L8_4W [All] p0 off: scope1count=1 scope1_0_kind=Board scope1_0_value=Board scope2count=1 scope2_0_kind=Board scope2_0_value=Board commentlength=93 gap=23.5 // Protel DXP Scope 2 Expression Was: InLayerClass('Bottom') and inpoly and not InNet('GND')
Clearance Clearance_TX_RX [All] p0 off: scope1count=1 scope1_0_kind=Board scope1_0_value=Board scope2count=1 scope2_0_kind=Board scope2_0_value=Board commentlength=44 gap=4 // Protel DXP Scope 2 Expression Was: isvia
Clearance Clearance_TX_RX [(InNetClass('TX') or InNetClass('RX')) and (istrack or IsArc or IsRegion) vs isvia] p1: gap=4 ignorepadtopadclearanceinfootprint=TRUE
Clearance Clearance_L3_4W [istrack and (InNetClass('12XX_CLOCK') or InNetClass('12XX_SYNC')) vs InLayerClass('L3') and inpoly] p2: gap=15.3 ignorepadtopadclearanceinfootprint=TRUE
Clearance Clearance_L6_4W [istrack and (InNetClass('12XX_CLOCK') or InNetClass('12XX_SYNC')) vs InLayerClass('L6') and inpoly] p3: gap=21 ignorepadtopadclearanceinfootprint=TRUE
Clearance Clearance_L8_4W [istrack and (InNetClass('12XX_CLOCK') or InNetClass('12XX_SYNC')) vs InLayerClass('Bottom') and inpoly and not InNet('GND')] p4: gap=23.5 ignorepadtopadclearanceinfootprint=TRUE
Clearance Clearance_GND-Pad [(WithinRoom('GND_Rule1') or WithinRoom('GND_Rule2') or WithinRoom('GND_Rule3') or WithinRoom('GND_Rule4')) and IsPad vs InPoly] p5: gap=9 ignorepadtopadclearanceinfootprint=TRUE
Clearance Clearance_L8_Diff_4W [InAnyDifferentialPair and IsTrack vs Istrack and InLayerClass('Bottom')] p6: gap=21 ignorepadtopadclearanceinfootprint=TRUE
Clearance Clearance_L6_Diff_4W [InAnyDifferentialPair and IsTrack vs Istrack and InLayerClass('L6')] p7: gap=16 ignorepadtopadclearanceinfootprint=TRUE
Clearance "Clearance_Power Divider_1" [isvia and InNetClass('FMCW') and (WithinRoom('Room5') OR WithinRoom('Room6')) vs InNet('GND') and InLayerClass('Top')  and InPoly] p8: gap=8 ignorepadtopadclearanceinfootprint=TRUE except(8.01: Via-Poly)
Clearance "Clearance_Power Divider" [InLayerClass('Top') and All and (WithinRoom('Room5') or WithinRoom('Room6'))] p9: gap=7 ignorepadtopadclearanceinfootprint=TRUE except(4.6: Via-Region; 5.9: Track-Via; 6.6: SMDPad-Poly SMDPad-Region; 8.01: Via-Poly)
Clearance Clearance_FMCW_L3_All_Room [InNetClass('FMCW') and (istrack or IsArc)  and InLayerClass('L3') vs IsVia and (WithinRoom('A1') or WithinRoom('A2') or WithinRoom('A3') or WithinRoom('A4') or WithinRoom('A5') or WithinRoom('A6') or WithinRoom('A7') or WithinRoom('A8') or WithinRoom('A9'))] p10: gap=8 ignorepadtopadclearanceinfootprint=TRUE
Clearance Clearance_FMCW_L3_All [InNetClass('FMCW') and (istrack or IsArc)  and InLayerClass('L3')] p11: gap=50 ignorepadtopadclearanceinfootprint=TRUE except(200: Arc-Poly Track-Poly)
Clearance Clearance_20GHz [IsRegion and InNetClass('20GHz') vs InPoly and InNet('GND')] p12: gap=7 ignorepadtopadclearanceinfootprint=TRUE
Clearance "Clearance_Internal Poly" [InPoly and InLayerClass('Internal') vs isvia and (WithinRoom('Room1') or WithinRoom('Room2') or WithinRoom('Room3') or WithinRoom('Room4'))] p13: gap=5 ignorepadtopadclearanceinfootprint=TRUE
Clearance Clearance_FMCW_L3_Poly [InLayerClass('L3') and InPoly vs (isarc or istrack) AND InNetClass('FMCW')] p14: gap=200 ignorepadtopadclearanceinfootprint=TRUE
Clearance Clearance_Keepout [IsKeepOut] p15: gap=1 ignorepadtopadclearanceinfootprint=TRUE except(0: Arc-SMDPad)
Clearance Clearance_Antenna [InNetClass('Antenna') vs InPoly and InNet('GND') and InLayerClass('Top')] p16: gap=10 ignorepadtopadclearanceinfootprint=FALSE except(4.16: Arc-Poly Track-Poly; 4.69: Poly-Region; 8.01: Via-Poly)
Clearance Clearance_Poly [All vs InPolygon] p17: gap=10 ignorepadtopadclearanceinfootprint=FALSE except(8: Via-Poly; 15: Poly-Poly Poly-Region)
Clearance Clearance_BGA [(WithinRoom('Room1') or WithinRoom('Room2') or WithinRoom('Room3') or WithinRoom('Room4')) and All] p18: gap=4 ignorepadtopadclearanceinfootprint=TRUE
Clearance [All] p19: gap=5 ignorepadtopadclearanceinfootprint=TRUE
ComponentClearance [All] p0: scope1count=1 scope1_0_kind=Board scope1_0_value=Board scope2count=1 scope2_0_kind=Board scope2_0_value=Board commentlength=0 gap=10 collisioncheckmode=3
DiffPairsRouting [All] p0: scope1count=1 scope1_0_kind=Board scope1_0_value=Board scope2count=1 scope2_0_kind=Board scope2_0_value=Board commentlength=0
DiffPairsRouting [All] p1: maxlimit=10 minlimit=5.5 mostfreqgap=7 toplayer_maxgap=5.5 toplayer_prefgap=5.5 toplayer_minwidth=4 toplayer_maxwidth=6.5 toplayer_prefwidth=6.5 midlayer1_prefgap=5.5 midlayer1_minwidth=4 midlayer1_maxwidth=15 midlayer1_prefwidth=15 midlayer2_prefgap=5.5 midlayer2_minwidth=4 midlayer2_maxwidth=15 midlayer2_prefwidth=15 midlayer3_prefgap=5.5 midlayer3_minwidth=4 midlayer3_maxwidth=15 midlayer3_prefwidth=15 midlayer4_prefgap=5.5 midlayer4_minwidth=4 midlayer4_maxwidth=15 midlayer4_prefwidth=15 midlayer5_mingap=7 midlayer5_maxgap=7 midlayer5_minwidth=5 midlayer5_maxwidth=5 midlayer5_prefwidth=5 midlayer6_prefgap=5.5 midlayer6_minwidth=4 midlayer6_maxwidth=15 midlayer6_prefwidth=15 bottomlayer_mingap=6.75 bottomlayer_maxgap=6.75 bottomlayer_prefgap=6.75 bottomlayer_minwidth=5.25 bottomlayer_maxwidth=5.25 bottomlayer_prefwidth=5.25 maxuncoupledlength=500
FabricationTestPointUsage [All] p0: scope1count=1 scope1_0_kind=Board scope1_0_value=Board scope2count=1 scope2_0_kind=Board scope2_0_value=Board commentlength=0 valid=0 allowmultiple=FALSE
FabricationTestpoint [All] p0: scope1count=1 scope1_0_kind=Board scope1_0_value=Board scope2count=1 scope2_0_kind=Board scope2_0_value=Board commentlength=0 side=3 testpointundercomponent=TRUE minsize=40 maxsize=100 preferedsize=60 minholesize=0 maxholesize=40 preferedholesize=32 testpointgrid=1
FanoutControl Fanout_BGA [All] p0 off: scope1count=1 scope1_0_kind=Board scope1_0_value=Board scope2count=1 scope2_0_kind=Board scope2_0_value=Board commentlength=69 // Protel DXP Scope 1 Expression Was: IsBGA   Fanout_BGA (Default Rule)
FanoutControl Fanout_LCC [All] p0 off: scope1count=1 scope1_0_kind=Board scope1_0_value=Board scope2count=1 scope2_0_kind=Board scope2_0_value=Board commentlength=69 // Protel DXP Scope 1 Expression Was: IsLCC   Fanout_LCC (Default Rule)
FanoutControl Fanout_SOIC [All] p0 off: scope1count=1 scope1_0_kind=Board scope1_0_value=Board scope2count=1 scope2_0_kind=Board scope2_0_value=Board commentlength=71 // Protel DXP Scope 1 Expression Was: IsSOIC   Fanout_SOIC (Default Rule)
FanoutControl Fanout_Small [All] p0 off: scope1count=1 scope1_0_kind=Board scope1_0_value=Board scope2count=1 scope2_0_kind=Board scope2_0_value=Board commentlength=84 // Protel DXP Scope 1 Expression Was: (CompPinCount < 5)   Fanout_Small (Default Rule)
FanoutControl Fanout_Default [All] p0: scope1count=1 scope1_0_kind=Board scope1_0_value=Board scope2count=1 scope2_0_kind=Board scope2_0_value=Board commentlength=30 // Fanout_Default (Default Rule)
Height [All] p0: scope1count=1 scope1_0_kind=Board scope1_0_value=Board scope2count=1 scope2_0_kind=Board scope2_0_value=Board commentlength=0
HoleSize [All] p0: scope1count=1 scope1_0_kind=Board scope1_0_value=Board scope2count=1 scope2_0_kind=Board scope2_0_value=Board commentlength=0 absolutevalues=TRUE maxlimit=200 minlimit=5.9 maxpercent=80.000 minpercent=20.000
HoleSize [All] p1: absolutevalues=TRUE maxlimit=200 minlimit=5.9 maxpercent=80.000 minpercent=20.000
HoleToHoleClearance [All] p0: scope1count=1 scope1_0_kind=Board scope1_0_value=Board scope2count=1 scope2_0_kind=Board scope2_0_value=Board commentlength=0
LayerPairs [All] p0: scope1count=1 scope1_0_kind=Board scope1_0_value=Board scope2count=1 scope2_0_kind=Board scope2_0_value=Board commentlength=0 enforce=TRUE
MinimumAnnularRing MinimumAnnularRing_Via [All] p0 off: scope1count=1 scope1_0_kind=Board scope1_0_value=Board scope2count=1 scope2_0_kind=Board scope2_0_value=Board commentlength=44 minimumring=3.9 // Protel DXP Scope 1 Expression Was: IsVia
MinimumAnnularRing [All] p0: scope1count=1 scope1_0_kind=Board scope1_0_value=Board scope2count=1 scope2_0_kind=Board scope2_0_value=Board commentlength=0 minimumring=7.5
MinimumAnnularRing MinimumAnnularRing_Via [IsVia] p1: minimumring=3.9
MinimumAnnularRing [All] p2: minimumring=7.5
MinimumSolderMaskSliver [All] p0: scope1count=1 scope1_0_kind=Board scope1_0_value=Board scope2count=1 scope2_0_kind=Board scope2_0_value=Board commentlength=0
MinimumSolderMaskSliver [All] p1: minsoldermaskwidth=4
NetAntennae [All] p0: scope1count=1 scope1_0_kind=Board scope1_0_value=Board scope2count=1 scope2_0_kind=Board scope2_0_value=Board commentlength=0
PasteMaskExpansion [All] p0: scope1count=1 scope1_0_kind=Board scope1_0_value=Board scope2count=1 scope2_0_kind=Board scope2_0_value=Board commentlength=0 expansion=0
PlaneClearance [All] p0: scope1count=1 scope1_0_kind=Board scope1_0_value=Board scope2count=1 scope2_0_kind=Board scope2_0_value=Board commentlength=0 clearance=20
PlaneConnect [All] p0: scope1count=1 scope1_0_kind=Board scope1_0_value=Board scope2count=1 scope2_0_kind=Board scope2_0_value=Board commentlength=0 planeconnectstyle=Direct reliefexpansion=20 reliefentries=4 reliefconductorwidth=10 reliefairgap=10
PlaneConnect [All] p1: planeconnectstyle=Direct reliefexpansion=20 reliefentries=4 reliefconductorwidth=10 reliefairgap=10
PolygonConnect [All] p0: scope1count=1 scope1_0_kind=Board scope1_0_value=Board scope2count=1 scope2_0_kind=Board scope2_0_value=Board commentlength=0 connectstyle=Direct reliefconductorwidth=25 reliefentries=4 polygonreliefangle="90 Angle"
PolygonConnect [All] p1: connectstyle=Direct reliefconductorwidth=25 reliefentries=4 polygonreliefangle="90 Angle" airgapwidth=10
RoomDefinition A9 [All] p0: scope1count=1 scope1_0_kind=Board scope1_0_value=Board scope2count=1 scope2_0_kind=Board scope2_0_value=Board commentlength=0 region_x1=50692368 region_y1=29118137 region_x2=53336086 region_y2=30250096 confinementstyle=ConfineOut
RoomDefinition A8 [All] p0: scope1count=1 scope1_0_kind=Board scope1_0_value=Board scope2count=1 scope2_0_kind=Board scope2_0_value=Board commentlength=0 region_x1=35220733 region_y1=44795351 region_x2=36772535 region_y2=46119555 confinementstyle=ConfineOut
RoomDefinition A7 [All] p0: scope1count=1 scope1_0_kind=Board scope1_0_value=Board scope2count=1 scope2_0_kind=Board scope2_0_value=Board commentlength=0 region_x1=48187540 region_y1=44875018 region_x2=49534335 region_y2=46335697 confinementstyle=ConfineOut
RoomDefinition A6 [All] p0: scope1count=1 scope1_0_kind=Board scope1_0_value=Board scope2count=1 scope2_0_kind=Board scope2_0_value=Board commentlength=0 region_x1=57998201 region_y1=49295653 region_x2=59412929 region_y2=51020381 confinementstyle=ConfineOut
RoomDefinition A5 [All] p0: scope1count=1 scope1_0_kind=Board scope1_0_value=Board scope2count=1 scope2_0_kind=Board scope2_0_value=Board commentlength=0 region_x1=47588894 region_y1=50955136 region_x2=48600124 region_y2=53079398 confinementstyle=ConfineOut
RoomDefinition A4 [All] p0: scope1count=1 scope1_0_kind=ComponentClass scope1_0_value="Components Class 2" scope2count=1 scope2_0_kind=Board scope2_0_value=Board commentlength=0 region_x1=40838232 region_y1=50554768 region_x2=45154811 region_y2=55740181 confinementstyle=ConfineIn
RoomDefinition A3 [All] p0: scope1count=1 scope1_0_kind=ComponentClass scope1_0_value="Components Class 1" scope2count=1 scope2_0_kind=Board scope2_0_value=Board commentlength=0 region_x1=36942126 region_y1=53236081 region_x2=40726669 region_y2=57397877 confinementstyle=ConfineIn
RoomDefinition A2 [All] p0: scope1count=1 scope1_0_kind=Board scope1_0_value=Board scope2count=1 scope2_0_kind=Board scope2_0_value=Board commentlength=0 region_x1=34195080 region_y1=49766275 region_x2=36711686 region_y2=52210708 confinementstyle=ConfineOut
RoomDefinition A1 [All] p0: scope1count=1 scope1_0_kind=Board scope1_0_value=Board scope2count=1 scope2_0_kind=Board scope2_0_value=Board commentlength=0 region_x1=22605865 region_y1=49353850 region_x2=24034183 region_y2=51056844 confinementstyle=ConfineOut
RoomDefinition GND_Rule2 [All] p0: scope1count=1 scope1_0_kind=Board scope1_0_value=Board scope2count=1 scope2_0_kind=Board scope2_0_value=Board commentlength=0 region_x1=34746716 region_y1=46145155 region_x2=35402030 region_y2=47056895 confinementstyle=ConfineOut
RoomDefinition Room6 [All] p0: scope1count=1 scope1_0_kind=ComponentClass scope1_0_value="Components Class 2" scope2count=1 scope2_0_kind=Board scope2_0_value=Board commentlength=0 region_x1=41474681 region_y1=51488354 region_x2=44628158 region_y2=55185852 confinementstyle=ConfineIn
RoomDefinition Room5 [All] p0: scope1count=1 scope1_0_kind=ComponentClass scope1_0_value="Components Class 1" scope2count=1 scope2_0_kind=Board scope2_0_value=Board commentlength=0 region_x1=37578500 region_y1=53862399 region_x2=40667781 region_y2=57433500 confinementstyle=ConfineIn
RoomDefinition Room2 [All] p0: scope1count=1 scope1_0_kind=ComponentClass scope1_0_value=Designator scope2count=1 scope2_0_kind=Board scope2_0_value=Board commentlength=0 region_x1=52612041 region_y1=44403279 region_x2=58782874 region_y2=49739800 confinementstyle=ConfineIn
RoomDefinition Room3 [All] p0: scope1count=1 scope1_0_kind=ComponentClass scope1_0_value=40MHZ_CLOCK scope2count=1 scope2_0_kind=Board scope2_0_value=Board commentlength=0 region_x1=42449226 region_y1=45513340 region_x2=48505967 region_y2=51566500 confinementstyle=ConfineIn
RoomDefinition GND_Rule1 [All] p0: scope1count=1 scope1_0_kind=Board scope1_0_value=Board scope2count=1 scope2_0_kind=Board scope2_0_value=Board commentlength=0 region_x1=23016880 region_y1=45244147 region_x2=23672194 region_y2=46155887 confinementstyle=ConfineOut
RoomDefinition GND_Rule3 [All] p0: scope1count=1 scope1_0_kind=Board scope1_0_value=Board scope2count=1 scope2_0_kind=Board scope2_0_value=Board commentlength=0 region_x1=47872386 region_y1=46100414 region_x2=48527700 region_y2=47012154 confinementstyle=ConfineOut
RoomDefinition GND_Rule4 [All] p0: scope1count=1 scope1_0_kind=Board scope1_0_value=Board scope2count=1 scope2_0_kind=Board scope2_0_value=Board commentlength=0 region_x1=57901994 region_y1=45159465 region_x2=58557308 region_y2=46071205 confinementstyle=ConfineOut
RoomDefinition Room4 [All] p0: scope1count=1 scope1_0_kind=ComponentClass scope1_0_value=Designator scope2count=1 scope2_0_kind=Board scope2_0_value=Board commentlength=0 region_x1=17755768 region_y1=44506170 region_x2=24203413 region_y2=50141959 confinementstyle=ConfineIn
RoomDefinition Room1 [All] p0: scope1count=1 scope1_0_kind=ComponentClass scope1_0_value=12XX_4 scope2count=1 scope2_0_kind=Board scope2_0_value=Board commentlength=0 region_x1=29571792 region_y1=45005500 region_x2=35635588 region_y2=51520700 confinementstyle=ConfineIn
RoomDefinition Room1 [InComponentClass('12XX_4')] p1: confinementstyle=ConfineIn formatcopy=TRUE lockcomponents=FALSE outline 2033.68,3387.07 2640.06,3387.07 2640.06,2735.55 2033.68,2735.55
RoomDefinition Room4 [InComponentClass('Designator')] p2: confinementstyle=ConfineIn formatcopy=TRUE lockcomponents=FALSE outline 852.08,3249.2 1434.07,3249.2 1496.84,3185.76 1496.84,2685.62 852.08,2685.62
RoomDefinition A9 [All] p3: confinementstyle=ConfineOut formatcopy=TRUE lockcomponents=FALSE outline 4145.74,1260.01 4410.11,1260.01 4410.11,1146.81 4145.74,1146.81
RoomDefinition A8 [All] p4: confinementstyle=ConfineOut formatcopy=TRUE lockcomponents=FALSE outline 2598.57,2846.96 2753.75,2846.96 2753.75,2714.54 2598.57,2714.54
RoomDefinition A7 [All] p5: confinementstyle=ConfineOut formatcopy=TRUE lockcomponents=FALSE outline 3895.25,2868.57 4029.93,2868.57 4029.93,2722.5 3895.25,2722.5
RoomDefinition A6 [All] p6: confinementstyle=ConfineOut formatcopy=TRUE lockcomponents=FALSE outline 4876.32,3337.04 5017.79,3337.04 5017.79,3164.57 4876.32,3164.57
RoomDefinition A5 [All] p7: confinementstyle=ConfineOut formatcopy=TRUE lockcomponents=FALSE outline 3835.39,3542.94 3936.51,3542.94 3936.51,3330.51 3835.39,3330.51
RoomDefinition A4 [InComponentClass('Components Class 2')] p8: confinementstyle=ConfineIn formatcopy=TRUE lockcomponents=FALSE outline 3175.56,3808.47 3477.72,3808.47 3591.98,3694.2 3591.98,3647.65 3434.55,3490.22 3434.55,3331.1 3393.93,3290.48 3368.53,3290.48 3338.06,3320.95 3338.06,3457.22 3160.32,3634.96 3160.32,3793.76 3175.58,3809.02
RoomDefinition A3 [InComponentClass('Components Class 1')] p9: confinementstyle=ConfineIn formatcopy=TRUE lockcomponents=FALSE outline 2770.93,3947.31 2798.41,3974.79 3136.7,3974.79 3149.17,3962.32 3149.17,3890.53 3050.37,3791.74 3050.37,3616.18 2992.8,3558.61 2941.62,3558.61 2933.1,3567.14 2933.1,3720.66 2770.71,3883.04 2770.71,3945.66
RoomDefinition A2 [All] p10: confinementstyle=ConfineOut formatcopy=TRUE lockcomponents=FALSE outline 2542.67,3455.84 2644.92,3455.84 2747.67,3353.09 2747.67,3279.13 2680.16,3211.63 2599.75,3211.63 2496.01,3315.37 2496.01,3409.93 2542.15,3456.07
RoomDefinition A1 [All] p11: confinementstyle=ConfineOut formatcopy=TRUE lockcomponents=FALSE outline 1337.09,3340.68 1479.92,3340.68 1479.92,3170.39 1337.09,3170.39
RoomDefinition GND_Rule4 [All] p12: confinementstyle=ConfineOut formatcopy=TRUE lockcomponents=FALSE outline 4866.7,2842.12 4932.23,2842.12 4932.23,2750.95 4866.7,2750.95
RoomDefinition GND_Rule3 [All] p13: confinementstyle=ConfineOut formatcopy=TRUE lockcomponents=FALSE outline 3863.74,2936.22 3929.27,2936.22 3929.27,2845.04 3863.74,2845.04
RoomDefinition GND_Rule1 [All] p14: confinementstyle=ConfineOut formatcopy=TRUE lockcomponents=FALSE outline 1378.19,2850.59 1443.72,2850.59 1443.72,2759.41 1378.19,2759.41
RoomDefinition GND_Rule2 [All] p15: confinementstyle=ConfineOut formatcopy=TRUE lockcomponents=FALSE outline 2551.17,2940.69 2616.7,2940.69 2616.7,2849.52 2551.17,2849.52
RoomDefinition Room6 [InComponentClass('Components Class 2')] p16: confinementstyle=ConfineIn formatcopy=TRUE lockcomponents=FALSE outline 3223.97,3753.59 3539.32,3753.59 3539.32,3383.84 3223.97,3383.84
RoomDefinition Room5 [InComponentClass('Components Class 1')] p17: confinementstyle=ConfineIn formatcopy=TRUE lockcomponents=FALSE outline 2834.35,3978.35 3143.28,3978.35 3143.28,3621.24 2834.35,3621.24
RoomDefinition Room2 [InComponentClass('Designator')] p18: confinementstyle=ConfineIn formatcopy=TRUE lockcomponents=FALSE outline 4337.7,3208.98 4954.79,3208.98 4954.79,2675.33 4337.7,2675.33
RoomDefinition Room3 [InComponentClass('40MHZ_CLOCK')] p19: confinementstyle=ConfineIn formatcopy=TRUE lockcomponents=FALSE outline 3321.42,3391.65 3927.1,3391.65 3927.1,2786.33 3321.42,2786.33
RoutingCorners [All] p0: scope1count=1 scope1_0_kind=Board scope1_0_value=Board scope2count=1 scope2_0_kind=Board scope2_0_value=Board commentlength=0 cornerstyle=45-Degree minsetback=100 maxsetback=100
RoutingLayers [All] p0: scope1count=1 scope1_0_kind=Board scope1_0_value=Board scope2count=1 scope2_0_kind=Board scope2_0_value=Board commentlength=0 top layer=Automatic mid layer 1=Automatic mid layer 2=Automatic mid layer 3=Automatic mid layer 4=Automatic mid layer 5=Automatic mid layer 6=Automatic bottom layer=Automatic
RoutingPriority [All] p0: scope1count=1 scope1_0_kind=Board scope1_0_value=Board scope2count=1 scope2_0_kind=Board scope2_0_value=Board commentlength=0
RoutingTopology [All] p0: scope1count=1 scope1_0_kind=Board scope1_0_value=Board scope2count=1 scope2_0_kind=Board scope2_0_value=Board commentlength=0 topology=Shortest
RoutingVias [All] p0: scope1count=1 scope1_0_kind=Board scope1_0_value=Board scope2count=1 scope2_0_kind=Board scope2_0_value=Board commentlength=0 holewidth=28 width=50 viastyle="Through Hole" minholewidth=5.8 minwidth=15 maxholewidth=28 maxwidth=50
RoutingVias [All] p1: holewidth=28 width=50 viastyle="Through Hole" minholewidth=5.8 minwidth=15 maxholewidth=28 maxwidth=50
ShortCircuit [All] p0: scope1count=1 scope1_0_kind=Board scope1_0_value=Board scope2count=1 scope2_0_kind=Board scope2_0_value=Board commentlength=0 allowed=FALSE
SilkToBoardRegionClearance [All] p0 off: scope1count=1 scope1_0_kind=Board scope1_0_value=Board scope2count=1 scope2_0_kind=Board scope2_0_value=Board commentlength=130 // Protel DXP Scope 1 Expression Was: Not ((IsComment or IsDesignator) And (Hide <> 'False')) and not InRegion(1000,500,4000,800)
SilkToBoardRegionClearance [Not ((IsComment or IsDesignator) And (Hide <> 'False')) and not InRegion(1000,500,4000,800)] p1:
SilkToSilkClearance [All] p0: scope1count=1 scope1_0_kind=Board scope1_0_value=Board scope2count=1 scope2_0_kind=Board scope2_0_value=Board commentlength=0
SilkToSilkClearance [All] p1: silktosilkclearance=3
SilkToSolderMaskClearance [All] p0 off: scope1count=1 scope1_0_kind=Board scope1_0_value=Board scope2count=1 scope2_0_kind=Board scope2_0_value=Board commentlength=44 // Protel DXP Scope 1 Expression Was: IsPad
SilkToSolderMaskClearance [IsPad] p1: minsilkscreentomaskgap=3 clearancetoexposedcopper=TRUE
SolderMaskExpansion [All] p0: scope1count=1 scope1_0_kind=Board scope1_0_value=Board scope2count=1 scope2_0_kind=Board scope2_0_value=Board commentlength=0 expansion=0
SolderMaskExpansion [All] p1: expansion=0
UnRoutedNet [All] p0: scope1count=1 scope1_0_kind=Board scope1_0_value=Board scope2count=1 scope2_0_kind=Board scope2_0_value=Board commentlength=0
UnpouredPolygon [All] p0: scope1count=1 scope1_0_kind=Board scope1_0_value=Board scope2count=1 scope2_0_kind=Board scope2_0_value=Board commentlength=0
Width [All] p0: scope1count=1 scope1_0_kind=Board scope1_0_value=Board scope2count=1 scope2_0_kind=Board scope2_0_value=Board commentlength=0 maxlimit=50 minlimit=4 preferedwidth=10
Width [All] p1: maxlimit=50 minlimit=4 preferedwidth=10
23 further rules are at their usual default settings.

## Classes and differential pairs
channel class PROC054D_AWR_Pull_Resistors: AWR_1 AWR_2 AWR_3 AWR_4
channel class PROC054D_AWR_Power_Decoupling: AWR_1 AWR_2 AWR_3 AWR_4
channel class PROC054D_AWR_Interfaces: AWR_1 AWR_2 AWR_3 AWR_4
net class PMIC_CLKOUT: AWR_1_PMIC_CLKOUT AWR_2_PMIC_CLKOUT AWR_3_PMIC_CLKOUT AWR_4_PMIC_CLKOUT
net class "GND SENSE": AWR_1_OSC_CLKOUT AWR_1_OSC_CLKOUT_CONN AWR_2_OSC_CLKOUT AWR_3_OSC_CLKOUT AWR_3_OSC_CLKOUT_CONN AWR_4_OSC_CLKOUT BUF_CLKOUT2_RS BUF_CLKOUT3 BUF_CLKOUT3_RS BUF_CLKOUT4_RS EXT_40M_BUF_AWR_1_RS
net class FMCW: AWR_1_FMCW_CLKOUT AWR_1_FMCW_SYNCOUT AWR_3_FMCW_CLKOUT
net class 20GHz: AWR_2_FMCW_CLKOUT AWR_2_FMCW_SYNCOUT AWR_3_FMCW_CLKOUT AWR_3_FMCW_SYNCOUT AWR_4_FMCW_CLKOUT AWR_4_FMCW_SYNCOUT
net class TX: AWR_TX1_1 AWR_TX1_2 AWR_TX1_3 AWR_TX1_4 AWR_TX2_1 AWR_TX2_2 AWR_TX2_3 AWR_TX2_4 AWR_TX3_1 AWR_TX3_2 AWR_TX3_3 AWR_TX3_4
net class RX: AWR_RX1_1 AWR_RX1_2 AWR_RX1_3 AWR_RX1_4 AWR_RX2_1 AWR_RX2_2 AWR_RX2_3 AWR_RX2_4 AWR_RX3_1 AWR_RX3_2 AWR_RX3_3 AWR_RX3_4 AWR_RX4_1 AWR_RX4_2 AWR_RX4_3 AWR_RX4_4
net class Non-imp: AWR_1_1V0_RF1_FILT AWR_1_1V0_RF2_FILT AWR_1_1V2_FILT AWR_1_1V8_FILT AWR_1_SCL AWR_1_SDA AWR_1V4_APLL_1 AWR_1V4_APLL_2 AWR_1V4_APLL_3 AWR_1V4_APLL_4 AWR_2_1V0_RF1_FILT AWR_2_1V0_RF2_FILT AWR_2_1V2_FILT AWR_2_1V8_FILT AWR_2_SCL AWR_2_SDA AWR_3_1V0_RF1_FILT AWR_3_1V0_RF2_FILT AWR_3_1V2_FILT AWR_3_1V8_FILT AWR_3_SCL AWR_3_SDA AWR_4_1V0_RF1_FILT AWR_4_1V0_RF2_FILT AWR_4_1V2_FILT AWR_4_1V8_FILT AWR_4_SCL AWR_4_SDA AWR_VBGAP_1 AWR_VBGAP_2 AWR_VBGAP_3 AWR_VBGAP_4 AWR_VOUT_PA_1 AWR_VOUT_PA_2 AWR_VOUT_PA_3 AWR_VOUT_PA_4 GND LMK1_1V8 LMK1_3V3 LMK2_3V3 NetC9_1 NetC37_2 NetC38_2 NetC49_2 NetC50_2 NetC95_2 NetC96_2 NetC107_2 NetC108_2 NetDS3_2 PMIC1_3V3 PMIC1_AWR_1_1V0 PMIC1_AWR_4_1V0 PMIC1_AWR_14_1V2 PMIC1_AWR_14_1V8 PMIC1_FB_B0 PMIC1_FB_B1 PMIC1_FB_B2 PMIC1_FB_B3 PMIC1_INTN PMIC1_PGOOD PMIC1_PGOOD_RS PMIC1_SW_B0 PMIC1_SW_B1 PMIC1_SW_B2 PMIC1_SW_B3 PMIC1_VANA PMIC1_VIN_B0 PMIC1_VIN_B1 PMIC1_VIN_B2 PMIC1_VIN_B3 PMIC2_3V3 PMIC2_AWR_2_1V0 PMIC2_AWR_3_1V0 PMIC2_AWR_23_1V2 PMIC2_AWR_23_1V8 PMIC2_FB_B0 PMIC2_FB_B1 PMIC2_FB_B2 PMIC2_FB_B3 PMIC2_INTN PMIC2_PGOOD PMIC2_PGOOD_RS PMIC2_SW_B0 PMIC2_SW_B1 PMIC2_SW_B2 PMIC2_SW_B3 PMIC2_VANA PMIC2_VIN_B0 PMIC2_VIN_B1 PMIC2_VIN_B2 PMIC2_VIN_B3 QSPI_FLASH_3V3_1 QSPI_FLASH_3V3_2 QSPI_FLASH_3V3_3 QSPI_FLASH_3V3_4 SDA_RS_1 SDA_RS_2 SDA_RS_3 SDA_RS_4 SYSTEM_1V8 SYSTEM_3V3 SYSTEM_3V3_LED SYSTEM_3V3_LED_PW SYSTEM_5V0 SYSTEM_5V0_LED SYSTEM_PGOOD SYSTEM_PGOOD2_GS TMP1_3V3 TMP2_3V3
net class Impedance: 40M_BUF_IN_PRIMAWRY 40M_BUF_IN_SECONDAWRY AWR_1_BSS_LOGGER AWR_1_CSI2_CLK_N AWR_1_CSI2_CLK_P AWR_1_CSI2_TX0_N AWR_1_CSI2_TX0_P AWR_1_CSI2_TX1_N AWR_1_CSI2_TX1_P AWR_1_CSI2_TX2_N AWR_1_CSI2_TX2_P AWR_1_CSI2_TX3_N AWR_1_CSI2_TX3_P AWR_1_DIG_SYNCIN AWR_1_DIG_SYNCIN_RS AWR_1_DIG_SYNCOUT AWR_1_FMCW_CLKOUT AWR_1_FMCW_SYNCOUT AWR_1_GPIO_0 AWR_1_GPIO_1 AWR_1_GPIO_2 AWR_1_LVDS_FRCLK_N AWR_1_LVDS_FRCLK_P AWR_1_LVDS_VALID_N AWR_1_LVDS_VALID_P AWR_1_MCU_CLKOUT AWR_1_MCU_CLKOUT_CONN AWR_1_MSS_LOGGER AWR_1_NERROR_IN AWR_1_NERROR_OUT AWR_1_NRST AWR_1_NRST_HOST AWR_1_NRST_HOST_GS AWR_1_NRST_LED AWR_1_NRST_LED_PW AWR_1_NRST_RS AWR_1_OSC_CLKOUT AWR_1_OSC_CLKOUT_CONN AWR_1_PMIC_CLKOUT AWR_1_SOP0_TDO AWR_1_SOP1_SYNCOUT AWR_1_SOP2_PMICCLKOUT AWR_1_SPI_CLK1 AWR_1_SPI_CS1 AWR_1_SPI_HOST_INTR1 AWR_1_SPI_MISO1 AWR_1_SPI_MOSI1 AWR_1_TCK AWR_1_TDI AWR_1_TDO AWR_1_TMS AWR_1_UART_RX AWR_1_UART_TX AWR_1_WARM_RST AWR_1_XTAL_CLKM AWR_1_XTAL_CLKP AWR_1_XTALP_RS AWR_1V4_SYNTH_1 AWR_1V4_SYNTH_2 AWR_1V4_SYNTH_3 AWR_1V4_SYNTH_4 AWR_2_BSS_LOGGER AWR_2_CSI2_CLK_N AWR_2_CSI2_CLK_P AWR_2_CSI2_TX0_N AWR_2_CSI2_TX0_P AWR_2_CSI2_TX1_N AWR_2_CSI2_TX1_P AWR_2_CSI2_TX2_N AWR_2_CSI2_TX2_P AWR_2_CSI2_TX3_N AWR_2_CSI2_TX3_P AWR_2_DIG_SYNCIN AWR_2_DIG_SYNCIN_RS AWR_2_DIG_SYNCOUT AWR_2_FMCW_CLKOUT AWR_2_FMCW_SYNCOUT AWR_2_GPIO_0 AWR_2_GPIO_1 AWR_2_GPIO_2 AWR_2_LVDS_FRCLK_N AWR_2_LVDS_FRCLK_P AWR_2_LVDS_VALID_N AWR_2_LVDS_VALID_P AWR_2_MCU_CLKOUT AWR_2_MSS_LOGGER AWR_2_NERROR_IN AWR_2_NERROR_OUT AWR_2_NRST AWR_2_NRST_HOST AWR_2_NRST_HOST_GS AWR_2_NRST_LED AWR_2_NRST_LED_PW AWR_2_NRST_RS AWR_2_OSC_CLKOUT AWR_2_PMIC_CLKOUT AWR_2_SOP0_TDO AWR_2_SOP1_SYNCOUT AWR_2_SOP2_PMICCLKOUT AWR_2_SPI_CLK1 AWR_2_SPI_CS1 AWR_2_SPI_HOST_INTR1 AWR_2_SPI_MISO1 AWR_2_SPI_MOSI1 AWR_2_TCK AWR_2_TDI AWR_2_TDO AWR_2_TMS AWR_2_UART_RX AWR_2_UART_TX AWR_2_WARM_RST AWR_2_XTAL_CLKM AWR_2_XTAL_CLKP AWR_3_BSS_LOGGER AWR_3_CSI2_CLK_N AWR_3_CSI2_CLK_P AWR_3_CSI2_TX0_N AWR_3_CSI2_TX0_P AWR_3_CSI2_TX1_N AWR_3_CSI2_TX1_P AWR_3_CSI2_TX2_N AWR_3_CSI2_TX2_P AWR_3_CSI2_TX3_N AWR_3_CSI2_TX3_P AWR_3_DIG_SYNCIN AWR_3_DIG_SYNCIN_RS AWR_3_DIG_SYNCOUT AWR_3_FMCW_CLKOUT AWR_3_FMCW_SYNCOUT AWR_3_GPIO_0 AWR_3_GPIO_1 AWR_3_GPIO_2 AWR_3_LVDS_FRCLK_N AWR_3_LVDS_FRCLK_P AWR_3_LVDS_VALID_N AWR_3_LVDS_VALID_P AWR_3_MCU_CLKOUT AWR_3_MSS_LOGGER AWR_3_NERROR_IN AWR_3_NERROR_OUT AWR_3_NRST AWR_3_NRST_HOST AWR_3_NRST_HOST_GS AWR_3_NRST_LED AWR_3_NRST_LED_PW AWR_3_NRST_RS AWR_3_OSC_CLKOUT AWR_3_OSC_CLKOUT_CONN AWR_3_PMIC_CLKOUT AWR_3_SOP0_TDO AWR_3_SOP1_SYNCOUT AWR_3_SOP2_PMICCLKOUT AWR_3_SPI_CLK1 AWR_3_SPI_CS1 AWR_3_SPI_HOST_INTR1 AWR_3_SPI_MISO1 AWR_3_SPI_MOSI1 AWR_3_TCK AWR_3_TDI AWR_3_TDO AWR_3_TMS AWR_3_UART_RX AWR_3_UART_TX AWR_3_WARM_RST AWR_3_XTAL_CLKM AWR_3_XTAL_CLKP AWR_3_XTALP_RS AWR_4_BSS_LOGGER AWR_4_CSI2_CLK_N AWR_4_CSI2_CLK_P AWR_4_CSI2_TX0_N AWR_4_CSI2_TX0_P AWR_4_CSI2_TX1_N AWR_4_CSI2_TX1_P AWR_4_CSI2_TX2_N AWR_4_CSI2_TX2_P AWR_4_CSI2_TX3_N AWR_4_CSI2_TX3_P AWR_4_DIG_SYNCIN AWR_4_DIG_SYNCIN_RS AWR_4_DIG_SYNCOUT AWR_4_FMCW_CLKOUT AWR_4_FMCW_SYNCOUT AWR_4_GPIO_0 AWR_4_GPIO_1 AWR_4_GPIO_2 AWR_4_LVDS_FRCLK_N AWR_4_LVDS_FRCLK_P AWR_4_LVDS_VALID_N AWR_4_LVDS_VALID_P AWR_4_MCU_CLKOUT AWR_4_MSS_LOGGER AWR_4_NERROR_IN AWR_4_NERROR_OUT AWR_4_NRST AWR_4_NRST_HOST AWR_4_NRST_HOST_GS AWR_4_NRST_LED AWR_4_NRST_LED_PW AWR_4_NRST_RS AWR_4_OSC_CLKOUT AWR_4_PMIC_CLKOUT AWR_4_SOP0_TDO AWR_4_SOP1_SYNCOUT AWR_4_SOP2_PMICCLKOUT AWR_4_SPI_CLK1 AWR_4_SPI_CS1 AWR_4_SPI_HOST_INTR1 AWR_4_SPI_MISO1 AWR_4_SPI_MOSI1 AWR_4_TCK AWR_4_TDI AWR_4_TDO AWR_4_TMS AWR_4_UART_RX AWR_4_UART_TX AWR_4_WARM_RST AWR_4_XTAL_CLKM AWR_4_XTAL_CLKP AWR_CONN_TP1 AWR_CONN_TP2 AWR_CONN_TP3 AWR_CONN_TP4 AWR_RX1_1 AWR_RX1_2 AWR_RX1_3 AWR_RX1_4 AWR_RX2_1 AWR_RX2_2 AWR_RX2_3 AWR_RX2_4 AWR_RX3_1 AWR_RX3_2 AWR_RX3_3 AWR_RX3_4 AWR_RX4_1 AWR_RX4_2 AWR_RX4_3 AWR_RX4_4 AWR_TX1_1 AWR_TX1_2 AWR_TX1_3 AWR_TX1_4 AWR_TX2_1 AWR_TX2_2 AWR_TX2_3 AWR_TX2_4 AWR_TX3_1 AWR_TX3_2 AWR_TX3_3 AWR_TX3_4 BSS_LOGGER_RS_1 BSS_LOGGER_RS_2 BSS_LOGGER_RS_3 BSS_LOGGER_RS_4 BUF_CLKOUT1 BUF_CLKOUT1_RS BUF_CLKOUT2_RS BUF_CLKOUT3 BUF_CLKOUT3_RS BUF_CLKOUT4_RS CONN_MONITOR_1 CONN_MONITOR_2 DIG_SYNC_SOURCE DIG_SYNCOUT_RS_1 DIG_SYNCOUT_RS_2 DIG_SYNCOUT_RS_3 DIG_SYNCOUT_RS_4 EXT_40M_BUF_AWR_1_RS EXT_40MHZ_CLK_1V8 EXT_DIG_SYNC GPADC1_1 GPADC1_2 GPADC1_3 GPADC1_4 GPADC1_CONN_1 GPADC1_CONN_2 GPADC1_CONN_3 GPADC1_CONN_4 GPADC2_1 GPADC2_2 GPADC2_3 GPADC2_4 GPADC2_CONN_1 GPADC2_CONN_2 GPADC2_CONN_3 GPADC2_CONN_4 GPADC3_1 GPADC3_2 GPADC3_3 GPADC3_4 GPADC3_CONN_1 GPADC3_CONN_2 GPADC3_CONN_3 GPADC3_CONN_4 GPADC4_1 GPADC4_2 GPADC4_3 GPADC4_4 GPADC4_CONN_1 GPADC4_CONN_2 GPADC4_CONN_3 GPADC4_CONN_4 GPADC5_1 GPADC5_2 GPADC5_3 GPADC5_4 GPADC5_CONN_1 GPADC5_CONN_2 GPADC5_CONN_3 GPADC5_CONN_4 GPADC6_1 GPADC6_2 GPADC6_3 GPADC6_4 GPADC6_CONN_1 GPADC6_CONN_2 GPADC6_CONN_3 GPADC6_CONN_4 LMK1_CLK_EN LMK1_CLK_SEL LMK1_nCLK LMK1_OE LMK2_CLK_EN LMK2_CLK_EN_N LMK2_CLK_EN_P LMK2_CLK_SEL LMK2_OE MCU_CLKOUT_RS_1 MCU_CLKOUT_RS_2 MCU_CLKOUT_RS_3 MCU_CLKOUT_RS_4 MSS_LOGGER_RS_1 MSS_LOGGER_RS_2 MSS_LOGGER_RS_3 MSS_LOGGER_RS_4 NERROR_OUT NERROR_OUT_LED NERROR_OUT_RS_1 NERROR_OUT_RS_2 NERROR_OUT_RS_3 NERROR_OUT_RS_4 NetDS4_2 NetDS5_2 NetDS6_2 NetDS7_2 OSC_CLKOUT_RS_1 OSC_CLKOUT_RS_2 OSC_CLKOUT_RS_3 OSC_CLKOUT_RS_4 PMIC1_GPIO2 PMIC1_GPIO3 PMIC1_SCL PMIC1_SDA PMIC2_GPIO2 PMIC2_GPIO3 PMIC2_TMPSNS_SCL PMIC2_TMPSNS_SDA PMIC_BUCK_EN PMIC_BUCKEN_CONN PMIC_CLKOUT_RS_1 PMIC_CLKOUT_RS_2 PMIC_CLKOUT_RS_3 PMIC_CLKOUT_RS_4 PMIC_NRST PMIC_NRST_CONN QSPI_CLK_1 QSPI_CLK_2 QSPI_CLK_3 QSPI_CLK_4 QSPI_CLK_RS_1 QSPI_CLK_RS_2 QSPI_CLK_RS_3 QSPI_CLK_RS_4 QSPI_CS_1 QSPI_CS_2 QSPI_CS_3 QSPI_CS_4 QSPI_CS_RS_1 QSPI_CS_RS_2 QSPI_CS_RS_3 QSPI_CS_RS_4 QSPI_D0_1 QSPI_D0_2 QSPI_D0_3 QSPI_D0_4 QSPI_D0_RS_1 QSPI_D0_RS_2 QSPI_D0_RS_3 QSPI_D0_RS_4 QSPI_D1_1 QSPI_D1_2 QSPI_D1_3 QSPI_D1_4 QSPI_D1_RS_1 QSPI_D1_RS_2 QSPI_D1_RS_3 QSPI_D1_RS_4 QSPI_D2_1 QSPI_D2_2 QSPI_D2_3 QSPI_D2_4 QSPI_D2_RS_1 QSPI_D2_RS_2 QSPI_D2_RS_3 QSPI_D2_RS_4 QSPI_D3_1 QSPI_D3_2 QSPI_D3_3 QSPI_D3_4 QSPI_D3_RS_1 QSPI_D3_RS_2 QSPI_D3_RS_3 QSPI_D3_RS_4 SPI_HOST_INTR1_RS_1 SPI_HOST_INTR1_RS_2 SPI_HOST_INTR1_RS_3 SPI_HOST_INTR1_RS_4 SPI_MISO1_RS_1 SPI_MISO1_RS_2 SPI_MISO1_RS_3 SPI_MISO1_RS_4 TDO_RS_1 TDO_RS_2 TDO_RS_3 TDO_RS_4 TMP1_ADD0 TMP2_ADD0 TMP_ALERT TMPSNS_ALERT TMPSNS_SCL TMPSNS_SDA UART_TX_RS_1 UART_TX_RS_2 UART_TX_RS_3 UART_TX_RS_4
net class SYSTEM_5V: SYSTEM_5V0
net class SYSTEM_5V_INPUT: PMIC1_VANA PMIC1_VIN_B0 PMIC1_VIN_B1 PMIC1_VIN_B2 PMIC1_VIN_B3 PMIC2_VANA PMIC2_VIN_B0 PMIC2_VIN_B1 PMIC2_VIN_B2 PMIC2_VIN_B3
net class SYSTEM_3V3: LMK1_3V3 LMK2_3V3 QSPI_FLASH_3V3_1 QSPI_FLASH_3V3_2 QSPI_FLASH_3V3_3 QSPI_FLASH_3V3_4 SYSTEM_3V3 TMP1_3V3 TMP2_3V3
net class SYSTEM_1V8: LMK1_1V8 SYSTEM_1V8
net class PMIC_OUTPUT: PMIC1_FB_B0 PMIC1_FB_B1 PMIC1_FB_B2 PMIC1_FB_B3 PMIC1_SW_B0 PMIC1_SW_B1 PMIC1_SW_B2 PMIC1_SW_B3 PMIC2_FB_B0 PMIC2_FB_B1 PMIC2_FB_B2 PMIC2_FB_B3 PMIC2_SW_B0 PMIC2_SW_B1 PMIC2_SW_B2 PMIC2_SW_B3
net class PMIC_CONTROL: AWR_1_PMIC_CLKOUT AWR_3_PMIC_CLKOUT PMIC1_GPIO2 PMIC1_GPIO3 PMIC1_INTN PMIC1_PGOOD_RS PMIC1_SCL PMIC1_SDA PMIC2_GPIO2 PMIC2_GPIO3 PMIC2_INTN PMIC2_PGOOD_RS PMIC2_TMPSNS_SCL PMIC2_TMPSNS_SDA PMIC_BUCK_EN PMIC_NRST
net class AWR_QSPI: QSPI_CLK_1 QSPI_CLK_2 QSPI_CLK_3 QSPI_CLK_4 QSPI_CLK_RS_1 QSPI_CLK_RS_2 QSPI_CLK_RS_3 QSPI_CLK_RS_4 QSPI_CS_1 QSPI_CS_2 QSPI_CS_3 QSPI_CS_4 QSPI_CS_RS_1 QSPI_CS_RS_2 QSPI_CS_RS_3 QSPI_CS_RS_4 QSPI_D0_1 QSPI_D0_2 QSPI_D0_3 QSPI_D0_4 QSPI_D1_1 QSPI_D1_2 QSPI_D1_3 QSPI_D1_4 QSPI_D2_1 QSPI_D2_2 QSPI_D2_3 QSPI_D2_4 QSPI_D3_1 QSPI_D3_2 QSPI_D3_3 QSPI_D3_4
net class AWR_POWER_ANA: AWR_1V4_APLL_1 AWR_1V4_APLL_2 AWR_1V4_APLL_3 AWR_1V4_APLL_4 AWR_1V4_SYNTH_1 AWR_1V4_SYNTH_2 AWR_1V4_SYNTH_3 AWR_1V4_SYNTH_4 AWR_VBGAP_1 AWR_VBGAP_2 AWR_VBGAP_3 AWR_VBGAP_4 AWR_VOUT_PA_1 AWR_VOUT_PA_2 AWR_VOUT_PA_3 AWR_VOUT_PA_4
net class AWR_GENERAL: AWR_1_BSS_LOGGER AWR_1_GPIO_0 AWR_1_GPIO_1 AWR_1_GPIO_2 AWR_1_MSS_LOGGER AWR_1_NERROR_IN AWR_1_NERROR_OUT AWR_1_NRST AWR_1_SCL AWR_1_SDA AWR_1_SPI_CLK1 AWR_1_SPI_CS1 AWR_1_SPI_HOST_INTR1 AWR_1_SPI_MISO1 AWR_1_SPI_MOSI1 AWR_1_UART_RX AWR_1_UART_TX AWR_1_WARM_RST AWR_2_BSS_LOGGER AWR_2_GPIO_0 AWR_2_GPIO_1 AWR_2_GPIO_2 AWR_2_MSS_LOGGER AWR_2_NERROR_IN AWR_2_NERROR_OUT AWR_2_NRST AWR_2_SCL AWR_2_SDA AWR_2_SPI_CLK1 AWR_2_SPI_CS1 AWR_2_SPI_HOST_INTR1 AWR_2_SPI_MISO1 AWR_2_SPI_MOSI1 AWR_2_UART_RX AWR_2_UART_TX AWR_2_WARM_RST AWR_3_BSS_LOGGER AWR_3_GPIO_0 AWR_3_GPIO_1 AWR_3_GPIO_2 AWR_3_MSS_LOGGER AWR_3_NERROR_IN AWR_3_NERROR_OUT AWR_3_NRST AWR_3_SCL AWR_3_SDA AWR_3_SPI_CLK1 AWR_3_SPI_CS1 AWR_3_SPI_HOST_INTR1 AWR_3_SPI_MISO1 AWR_3_SPI_MOSI1 AWR_3_UART_RX AWR_3_UART_TX AWR_3_WARM_RST AWR_4_BSS_LOGGER AWR_4_GPIO_0 AWR_4_GPIO_1 AWR_4_GPIO_2 AWR_4_MSS_LOGGER AWR_4_NERROR_IN AWR_4_NERROR_OUT AWR_4_NRST AWR_4_SCL AWR_4_SDA AWR_4_SPI_CLK1 AWR_4_SPI_CS1 AWR_4_SPI_HOST_INTR1 AWR_4_SPI_MISO1 AWR_4_SPI_MOSI1 AWR_4_UART_RX AWR_4_UART_TX AWR_4_WARM_RST BSS_LOGGER_RS_1 BSS_LOGGER_RS_2 BSS_LOGGER_RS_3 BSS_LOGGER_RS_4 MSS_LOGGER_RS_1 MSS_LOGGER_RS_2 MSS_LOGGER_RS_3 MSS_LOGGER_RS_4 NERROR_OUT_RS_1 NERROR_OUT_RS_2 NERROR_OUT_RS_3 NERROR_OUT_RS_4 SDA_RS_1 SDA_RS_2 SDA_RS_3 SDA_RS_4 SPI_HOST_INTR1_RS_1 SPI_HOST_INTR1_RS_2 SPI_HOST_INTR1_RS_3 SPI_HOST_INTR1_RS_4 SPI_MISO1_RS_1 SPI_MISO1_RS_2 SPI_MISO1_RS_3 SPI_MISO1_RS_4 UART_TX_RS_1 UART_TX_RS_2 UART_TX_RS_3 UART_TX_RS_4
net class AWR_DEBUG: GPADC1_1 GPADC1_2 GPADC1_3 GPADC1_4 GPADC1_CONN_1 GPADC1_CONN_2 GPADC1_CONN_3 GPADC1_CONN_4 GPADC2_1 GPADC2_2 GPADC2_3 GPADC2_4 GPADC2_CONN_1 GPADC2_CONN_2 GPADC2_CONN_3 GPADC2_CONN_4 GPADC3_1 GPADC3_2 GPADC3_3 GPADC3_4 GPADC3_CONN_1 GPADC3_CONN_2 GPADC3_CONN_3 GPADC3_CONN_4 GPADC4_1 GPADC4_2 GPADC4_3 GPADC4_4 GPADC4_CONN_1 GPADC4_CONN_2 GPADC4_CONN_3 GPADC4_CONN_4 GPADC5_1 GPADC5_2 GPADC5_3 GPADC5_4 GPADC5_CONN_1 GPADC5_CONN_2 GPADC5_CONN_3 GPADC5_CONN_4 GPADC6_1 GPADC6_2 GPADC6_3 GPADC6_4 GPADC6_CONN_1 GPADC6_CONN_2 GPADC6_CONN_3 GPADC6_CONN_4
net class AWR_ANTENNA: AWR_RX1_1 AWR_RX1_2 AWR_RX1_3 AWR_RX1_4 AWR_RX2_1 AWR_RX2_2 AWR_RX2_3 AWR_RX2_4 AWR_RX3_1 AWR_RX3_2 AWR_RX3_3 AWR_RX3_4 AWR_RX4_1 AWR_RX4_2 AWR_RX4_3 AWR_RX4_4 AWR_TX1_1 AWR_TX1_2 AWR_TX1_3 AWR_TX1_4 AWR_TX2_1 AWR_TX2_2 AWR_TX2_3 AWR_TX2_4 AWR_TX3_1 AWR_TX3_2 AWR_TX3_3 AWR_TX3_4
net class AWR23_POWER_1V8: PMIC2_AWR_23_1V8
net class AWR23_POWER_1V2: PMIC2_AWR_23_1V2
net class AWR14_POWER_1V8: PMIC1_AWR_14_1V8
net class AWR14_POWER_1V2: PMIC1_AWR_14_1V2
net class AWR_4_POWER_RF: AWR_4_1V0_RF1_FILT AWR_4_1V0_RF2_FILT
net class AWR_3_POWER_RF: AWR_3_1V0_RF1_FILT AWR_3_1V0_RF2_FILT
net class AWR2_POWER_RF: PMIC2_AWR_2_1V0
net class AWR_2_POWER_1V0_RF: AWR_2_1V0_RF1_FILT AWR_2_1V0_RF2_FILT
net class AWR1_POWER_RF: PMIC1_AWR_1_1V0
net class AWR_SAFETY: NERROR_OUT TMPSNS_ALERT
net class AWR_3_CSI_LVDS: AWR_3_CSI2_CLK_N AWR_3_CSI2_CLK_P AWR_3_CSI2_TX0_N AWR_3_CSI2_TX0_P AWR_3_CSI2_TX1_N AWR_3_CSI2_TX1_P AWR_3_CSI2_TX2_N AWR_3_CSI2_TX2_P AWR_3_CSI2_TX3_N AWR_3_CSI2_TX3_P AWR_3_LVDS_FRCLK_N AWR_3_LVDS_FRCLK_P AWR_3_LVDS_VALID_N AWR_3_LVDS_VALID_P
net class AWR_3_SOP_RESET: AWR_3_NRST_HOST AWR_3_SOP0_TDO AWR_3_SOP1_SYNCOUT AWR_3_SOP2_PMICCLKOUT AWR_3_WARM_RST
net class AWR_2_JTAG: AWR_2_TCK AWR_2_TDI AWR_2_TDO AWR_2_TMS
net class AWR_3_GENERAL: AWR_3_BSS_LOGGER AWR_3_GPIO_0 AWR_3_GPIO_1 AWR_3_GPIO_2 AWR_3_MSS_LOGGER AWR_3_SPI_CLK1 AWR_3_SPI_CS1 AWR_3_SPI_HOST_INTR1 AWR_3_SPI_MISO1 AWR_3_SPI_MOSI1 AWR_3_UART_RX AWR_3_UART_TX
net class AWR_2_CSI_LVDS: AWR_2_CSI2_CLK_N AWR_2_CSI2_CLK_P AWR_2_CSI2_TX0_N AWR_2_CSI2_TX0_P AWR_2_CSI2_TX1_N AWR_2_CSI2_TX1_P AWR_2_CSI2_TX2_N AWR_2_CSI2_TX2_P AWR_2_CSI2_TX3_N AWR_2_CSI2_TX3_P AWR_2_LVDS_FRCLK_N AWR_2_LVDS_FRCLK_P AWR_2_LVDS_VALID_N AWR_2_LVDS_VALID_P
net class AWR_3_JTAG: AWR_3_TCK AWR_3_TDI AWR_3_TDO AWR_3_TMS
net class AWR_4_CSI_LVDS: AWR_4_CSI2_CLK_N AWR_4_CSI2_CLK_P AWR_4_CSI2_TX0_N AWR_4_CSI2_TX0_P AWR_4_CSI2_TX1_N AWR_4_CSI2_TX1_P AWR_4_CSI2_TX2_N AWR_4_CSI2_TX2_P AWR_4_CSI2_TX3_N AWR_4_CSI2_TX3_P AWR_4_LVDS_FRCLK_N AWR_4_LVDS_FRCLK_P AWR_4_LVDS_VALID_N AWR_4_LVDS_VALID_P
net class AWR_1_SOP_RESET: AWR_1_NRST_HOST AWR_1_SOP0_TDO AWR_1_SOP1_SYNCOUT AWR_1_SOP2_PMICCLKOUT AWR_1_WARM_RST
net class AWR_1_JTAG: AWR_1_TCK AWR_1_TDI AWR_1_TDO AWR_1_TMS
net class AWR_1_GENERAL: AWR_1_BSS_LOGGER AWR_1_GPIO_0 AWR_1_GPIO_1 AWR_1_GPIO_2 AWR_1_MSS_LOGGER AWR_1_SPI_CLK1 AWR_1_SPI_CS1 AWR_1_SPI_HOST_INTR1 AWR_1_SPI_MISO1 AWR_1_SPI_MOSI1 AWR_1_UART_RX AWR_1_UART_TX
net class AWR_1_CSI_LVDS: AWR_1_CSI2_CLK_N AWR_1_CSI2_CLK_P AWR_1_CSI2_TX0_N AWR_1_CSI2_TX0_P AWR_1_CSI2_TX1_N AWR_1_CSI2_TX1_P AWR_1_CSI2_TX2_N AWR_1_CSI2_TX2_P AWR_1_CSI2_TX3_N AWR_1_CSI2_TX3_P AWR_1_LVDS_FRCLK_N AWR_1_LVDS_FRCLK_P AWR_1_LVDS_VALID_N AWR_1_LVDS_VALID_P
component class SYSTEM_POWER: C94 C149 C162 C163 C164 C165 C205 C206 R37 R38 R53 R61 R62 R77 R86 R87 R88 R89 R90 R91 R92 R93 R189 R190 R191 R204 R205 R206 R207 R208 R209 R210 R211 R212 U6 U11 U12 U13
component class SYSTEM_LED_INDICATORS: DS1 DS2 DS3 DS4 DS5 DS6 DS7 Q1 Q2 Q3 Q4 Q5 R192 R193 R194 R195 R196 R197 R198 R199 R200 R201 R202 R203
component class SYSTEM_3V3_SUPPLY: C9 C202 C203 U5
component class HOST_CONNECTORS: C190 C191 C192 C193 C194 J4 J5 J6 R19 R20 R98 R99 R100 R101 R102 R112 R114 R125 R145 R146 R147 R148 R149 R150 R151 R152 R153 R154 R155 R156 R157 R158 R159 R160 R161 R162 R163 TP8 TP12 TP13 TP15 TP16 TP17 TP18 TP19 TP20 TP25 TP29 TP30 TP32 TP33
component class Header: J1_1 J1_2 J1_3 J1_4 J2
component class DIG_SYNC_LO_20GHZ: C181 C182 C183 C184 C185 C186 C187 C188 C189 L35 R132 R133 R134 R135 R136 R137 R138 R139 R140 R141 R142 R143 R144 U8
component class SYSTEM_TEST_CONN_TERMINATION: J2 J3 R79 R82 R83 R84 R85 R186 R187
component class 40MHZ_CLOCK: C167 C168 C169 C170 C171 C172 C173 C174 C175 C176 C177 C178 C179 C180 L33 L34 R103 R104 R105 R106 R107 R108 R109 R110 R111 R113 R115 R116 R117 R118 R119 R120 R121 R122 R123 R124 R126 R127 R128 R129 R130 R131 R213 R214 U7 Y1 Y2
component class AWR_4: C1_4 C2_4 C3_4 C4_4 C5_4 C6_4 C7_4 C8_4 J1_4 R1_4 R2_4 R3_4 R4_4 R5_4 R6_4 R7_4 R8_4 R9_4 R10_4 R11_4 R12_4 R13_4 R14_4 R15_4 R16_4 R17_4 R18_4 R21_4 R22_4 R23_4 R24_4 R25_4 R26_4 R27_4 R28_4 R29_4 R30_4 R31_4 R32_4 R33_4 R188_4 TP1_4 TP2_4 TP3_4 U1_4 U2_4
component class AWR_3: C1_3 C2_3 C3_3 C4_3 C5_3 C6_3 C7_3 C8_3 J1_3 R1_3 R2_3 R3_3 R4_3 R5_3 R6_3 R7_3 R8_3 R9_3 R10_3 R11_3 R12_3 R13_3 R14_3 R15_3 R16_3 R17_3 R18_3 R21_3 R22_3 R23_3 R24_3 R25_3 R26_3 R27_3 R28_3 R29_3 R30_3 R31_3 R32_3 R33_3 R188_3 TP1_3 TP2_3 TP3_3 U1_3 U2_3
component class AWR_2: C1_2 C2_2 C3_2 C4_2 C5_2 C6_2 C7_2 C8_2 J1_2 R1_2 R2_2 R3_2 R4_2 R5_2 R6_2 R7_2 R8_2 R9_2 R10_2 R11_2 R12_2 R13_2 R14_2 R15_2 R16_2 R17_2 R18_2 R21_2 R22_2 R23_2 R24_2 R25_2 R26_2 R27_2 R28_2 R29_2 R30_2 R31_2 R32_2 R33_2 R188_2 TP1_2 TP2_2 TP3_2 U1_2 U2_2
component class AWR_2_AWR_3_LP87524P: C95 C96 C97 C98 C99 C100 C101 C102 C103 C104 C105 C106 C107 C108 C109 C110 C111 C112 C113 C114 C115 C116 C117 C118 C119 C120 C121 C122 C123 C124 C125 C126 C127 L25 L26 L27 L28 L29 L30 L31 L32 R59 R60 R63 R64 R65 R66 R67 R68 R69 R70 R71 R72 R74 R75 R76 R78 R80 R81 R95 R97 TP21 TP22 TP23 TP24 TP26 TP27 TP28 TP31 U4
component class AWR_2_AWR_3_LC_Filtering: C70 C71 C72 C73 C74 C75 C76 C77 C79 C80 C82 C83 C84 C85 C87 C88 C90 C91 C92 C93 C153 C154 C155 C156 C157 C158 C159 C160 C166 C201 C204 C207 L17 L18 L19 L20 L21 L22 L23 L24
component class AWR_1: C1_1 C2_1 C3_1 C4_1 C5_1 C6_1 C7_1 C8_1 J1_1 R1_1 R2_1 R3_1 R4_1 R5_1 R6_1 R7_1 R8_1 R9_1 R10_1 R11_1 R12_1 R13_1 R14_1 R15_1 R16_1 R17_1 R18_1 R21_1 R22_1 R23_1 R24_1 R25_1 R26_1 R27_1 R28_1 R29_1 R30_1 R31_1 R32_1 R33_1 R188_1 TP1_1 TP2_1 TP3_1 U1_1 U2_1
component class AWR_1_AWR_4_LP87524P: C37 C38 C39 C40 C41 C42 C43 C44 C45 C46 C47 C48 C49 C50 C51 C52 C53 C54 C55 C56 C57 C58 C59 C60 C61 C62 C63 C64 C65 C66 C67 C68 C69 L9 L10 L11 L12 L13 L14 L15 L16 R34 R36 R39 R40 R41 R42 R43 R44 R45 R46 R47 R48 R49 R50 R51 R52 R54 R55 R56 R57 R58 R73 R94 R96 TP4 TP5 TP6 TP7 TP9 TP10 TP11 TP14 U3
component class AWR_1_AWR_4_LC_Filtering: C10 C11 C12 C13 C14 C15 C16 C17 C18 C19 C20 C21 C22 C23 C24 C25 C26 C27 C28 C29 C30 C31 C32 C33 C34 C35 C36 C78 C81 C86 C89 C150 C151 C152 C161 L1 L2 L3 L4 L5 L6 L7 L8 R35
component class AssemblyNote: ZZ1 ZZ2 ZZ3 ZZ4
component class FiducialMark: FID1 FID2 FID3 FID4 FID5 FID6
component class EVM_HARDWARE: FID1 FID2 FID3 FID4 FID5 FID6 Logo1 Logo2 Logo3 Logo4 Logo5 LOGO6 ZZ1 ZZ2 ZZ3 ZZ4
component class Logo: Logo2
net class AWR_1_POWER_1V0_RF: AWR_1_1V0_RF1_FILT AWR_1_1V0_RF2_FILT
net class AWR_1_POWER_1V2: AWR_1_1V2_FILT
net class AWR_1_POWER_1V8: AWR_1_1V8_FILT
net class AWR_2_POWER_1V2: AWR_2_1V2_FILT
net class AWR_3_POWER_1V2: AWR_3_1V2_FILT
net class AWR_3_POWER_1V8: AWR_2_1V8_FILT AWR_3_1V8_FILT
net class AWR3_POWER_RF: PMIC2_AWR_3_1V0
net class AWR_4_POWER_1V2: AWR_4_1V2_FILT
net class AWR_4_POWER_1V8: AWR_4_1V8_FILT
net class AWR4_POWER_RF: PMIC1_AWR_4_1V0
net class AWR_20GHZ_LO: AWR_1_FMCW_CLKOUT AWR_1_FMCW_SYNCOUT AWR_2_FMCW_CLKOUT AWR_2_FMCW_SYNCOUT AWR_3_FMCW_CLKOUT AWR_3_FMCW_SYNCOUT AWR_4_FMCW_CLKOUT AWR_4_FMCW_SYNCOUT
component class SYSTEM_TEMP_SENSORS: C195 C196 C197 C198 C199 C200 R164 R165 R166 R167 R168 R169 R170 R171 R172 R173 U9 U10
net class Antenna: AWR_1_FMCW_CLKOUT AWR_1_FMCW_SYNCOUT AWR_2_FMCW_CLKOUT AWR_2_FMCW_SYNCOUT AWR_3_FMCW_CLKOUT AWR_3_FMCW_SYNCOUT AWR_4_FMCW_CLKOUT AWR_4_FMCW_SYNCOUT AWR_RX1_1 AWR_RX1_2 AWR_RX1_3 AWR_RX1_4 AWR_RX2_1 AWR_RX2_2 AWR_RX2_3 AWR_RX2_4 AWR_RX3_1 AWR_RX3_2 AWR_RX3_3 AWR_RX3_4 AWR_RX4_1 AWR_RX4_2 AWR_RX4_3 AWR_RX4_4 AWR_TX1_1 AWR_TX1_2 AWR_TX1_3 AWR_TX1_4 AWR_TX2_1 AWR_TX2_2 AWR_TX2_3 AWR_TX2_4 AWR_TX3_1 AWR_TX3_2 AWR_TX3_3 AWR_TX3_4
net class AWR2_SOP_RESET: AWR_2_NRST_HOST AWR_2_SOP0_TDO AWR_2_SOP1_SYNCOUT AWR_2_SOP2_PMICCLKOUT AWR_2_WARM_RST
net class AWR_2_GENERAL: AWR_2_BSS_LOGGER AWR_2_GPIO_0 AWR_2_GPIO_1 AWR_2_GPIO_2 AWR_2_MSS_LOGGER AWR_2_SPI_CLK1 AWR_2_SPI_CS1 AWR_2_SPI_HOST_INTR1 AWR_2_SPI_MISO1 AWR_2_SPI_MOSI1 AWR_2_UART_RX AWR_2_UART_TX
net class AWR_4_GENERAL: AWR_4_BSS_LOGGER AWR_4_GPIO_0 AWR_4_GPIO_1 AWR_4_GPIO_2 AWR_4_MSS_LOGGER AWR_4_SPI_CLK1 AWR_4_SPI_CS1 AWR_4_SPI_HOST_INTR1 AWR_4_SPI_MISO1 AWR_4_SPI_MOSI1 AWR_4_UART_RX AWR_4_UART_TX
net class AWR_4_JTAG: AWR_4_TCK AWR_4_TDI AWR_4_TDO AWR_4_TMS
net class AWR_4_SOP_RESET: AWR_4_NRST_HOST AWR_4_SOP0_TDO AWR_4_SOP1_SYNCOUT AWR_4_SOP2_PMICCLKOUT AWR_4_WARM_RST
